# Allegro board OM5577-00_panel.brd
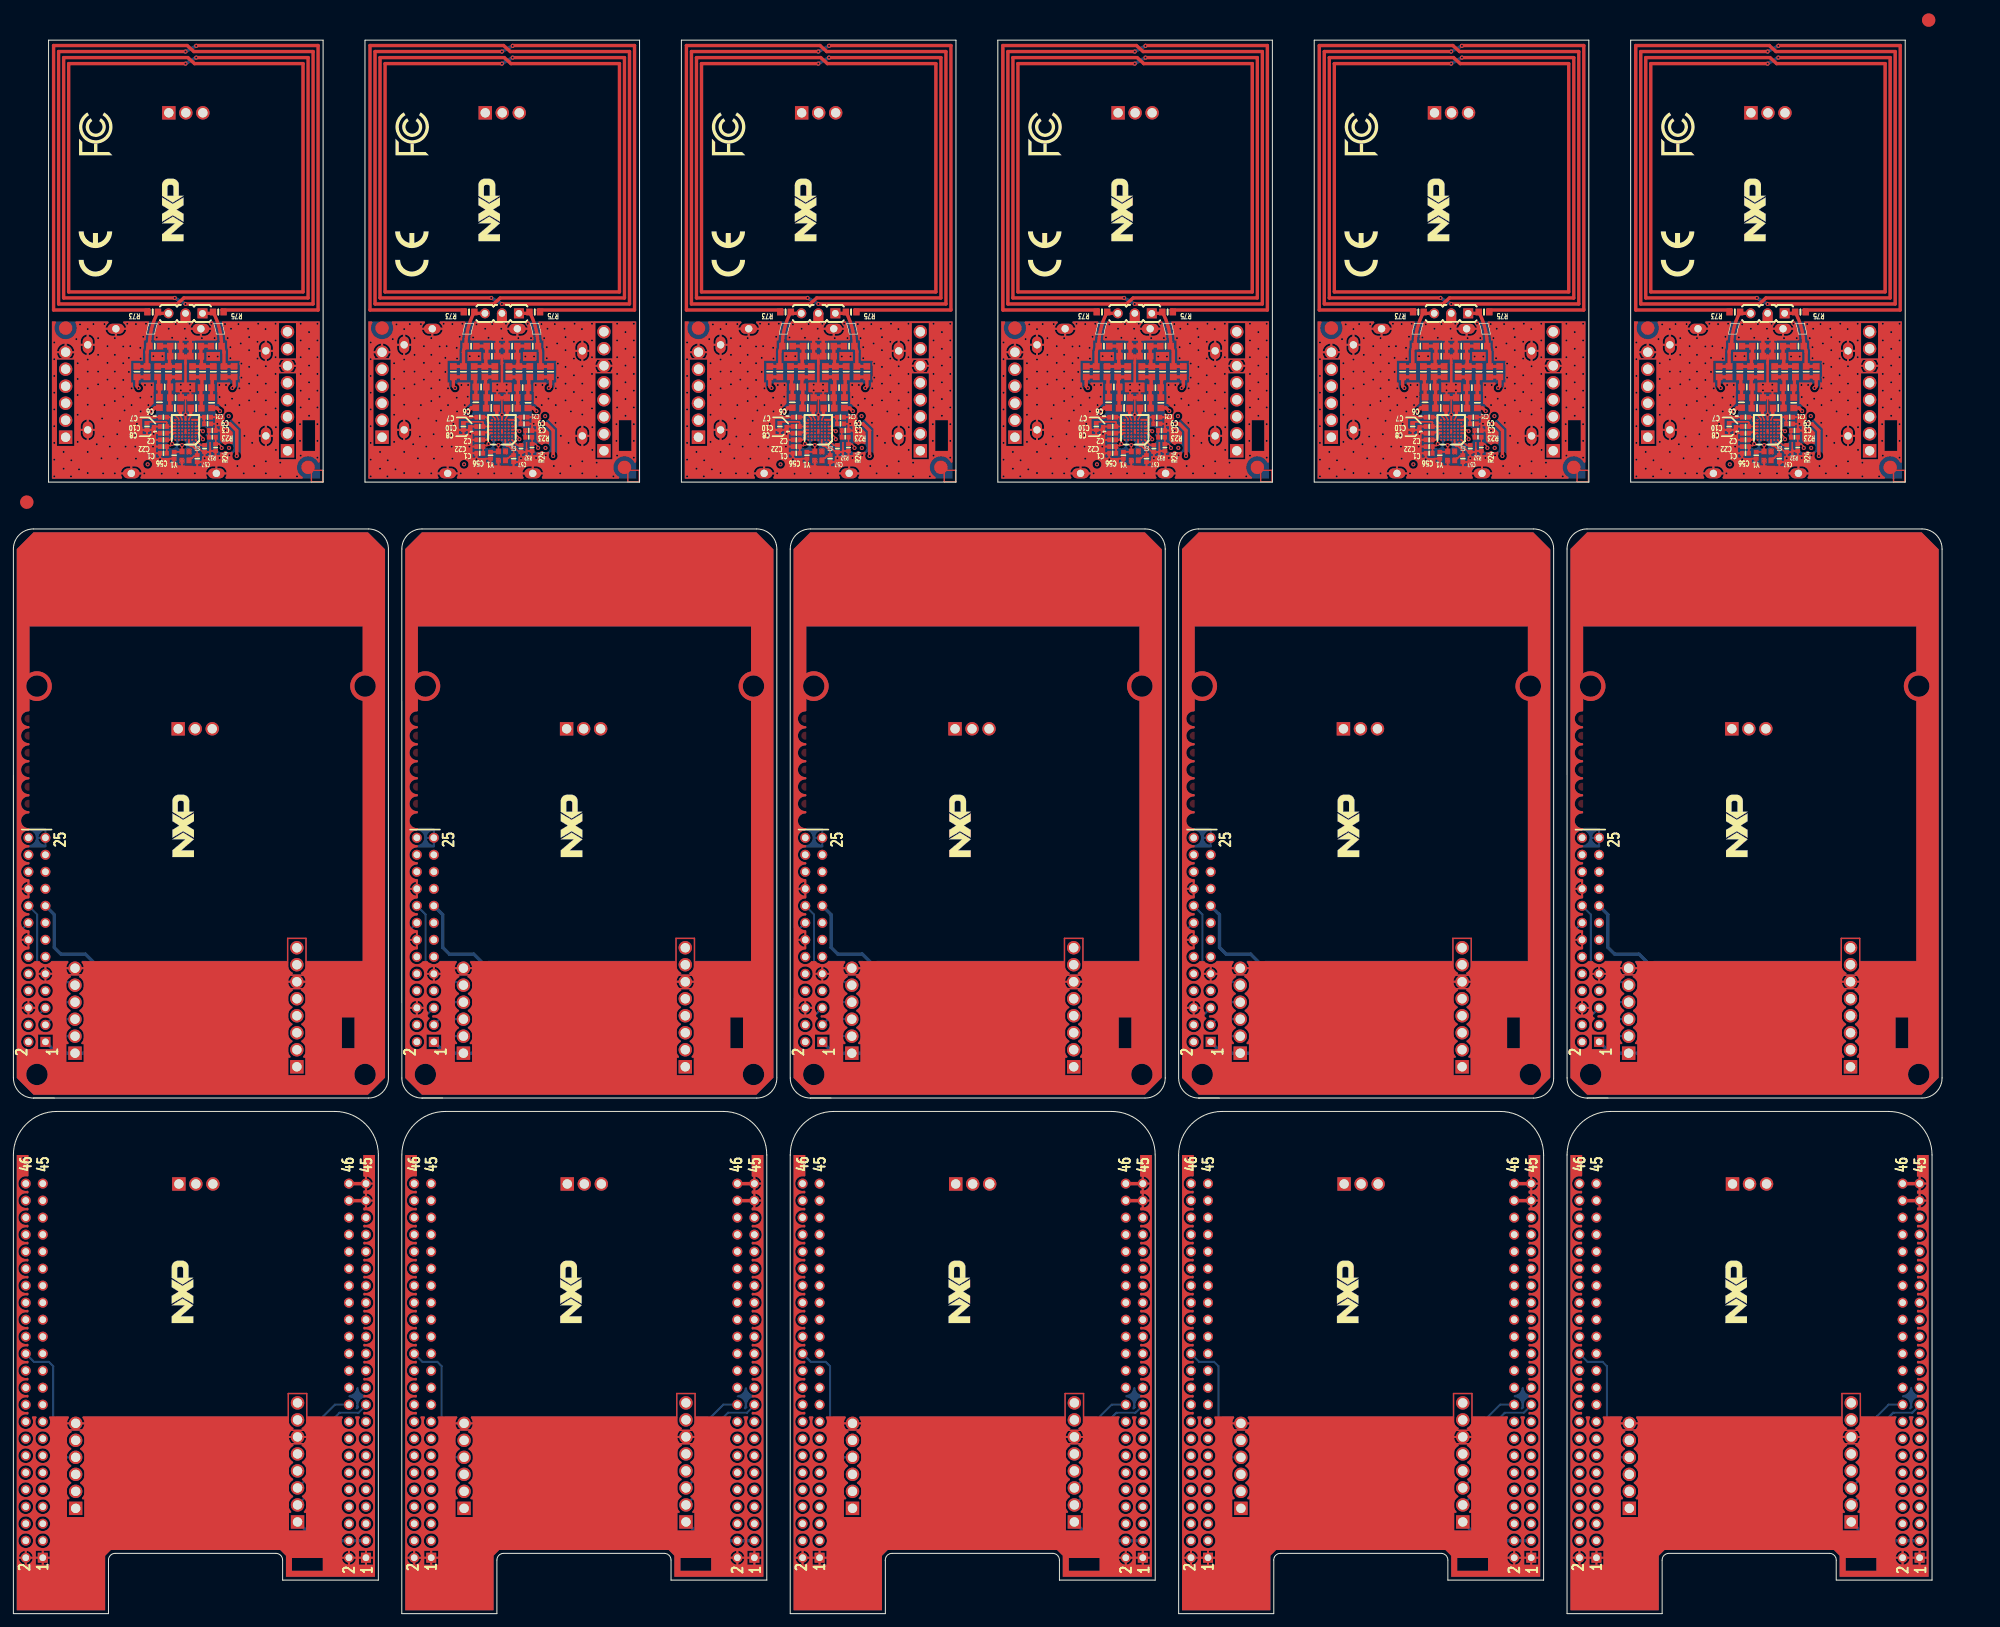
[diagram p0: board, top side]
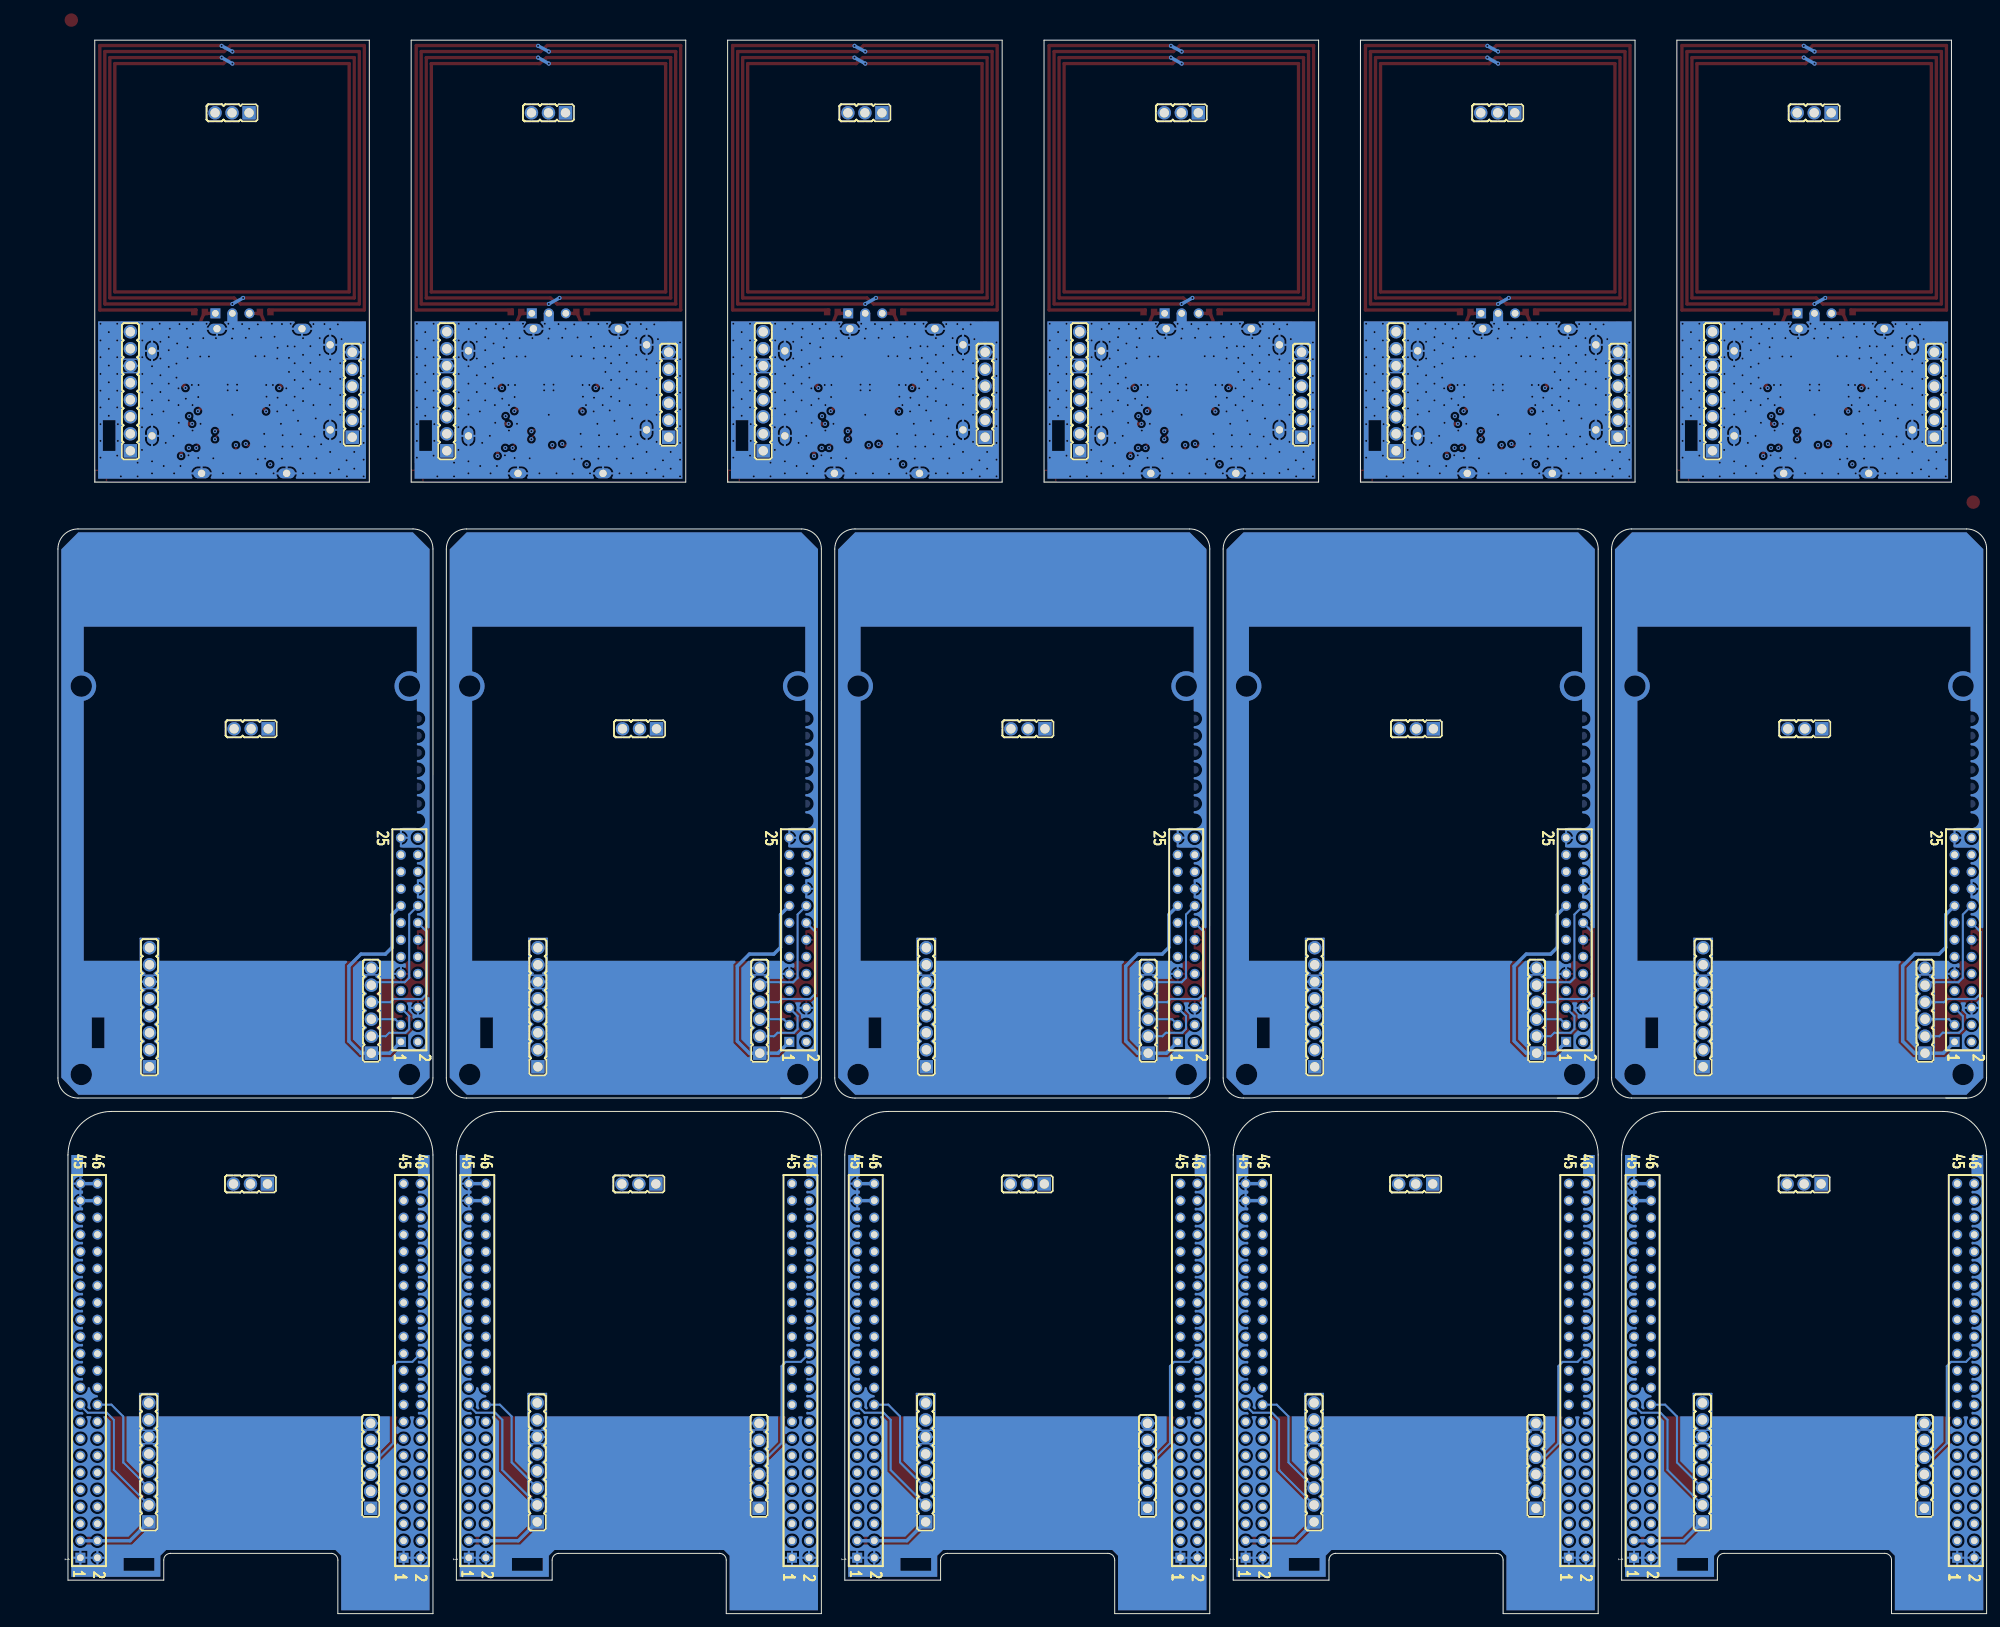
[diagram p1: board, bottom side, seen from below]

Outline 288 x 235 mm; copper layers: TOP, IS1, IS2, BOTTOM. Coordinates in mm from the lower left corner of the outline.
Outline path: 3,77 arc(0.88,77.88) 0,80 0,159 arc(0.88,161.12) 3,162 53,162 arc(55.12,161.12) 56,159 56,80 arc(55.12,77.88) 53,77 3,77 ; 3,77 6.1,77 ; 61,77 arc(58.88,77.88) 58,80 58,159 arc(58.88,161.12) 61,162 111,162 arc(113.12,161.12) 114,159 114,80 arc(113.12,77.88) 111,77 61,77 ; 61,77 64.1,77 ; 119,77 arc(116.88,77.88) 116,80 116,159 arc(116.88,161.12) 119,162 169,162 arc(171.12,161.12) 172,159 172,80 arc(171.12,77.88) 169,77 119,77 ; 119,77 122.1,77 ; 177,77 arc(174.88,77.88) 174,80 174,159 arc(174.88,161.12) 177,162 227,162 arc(229.12,161.12) 230,159 230,80 arc(229.12,77.88) 227,77 177,77 ; 177,77 180.1,77 ; 235,77 arc(232.88,77.88) 232,80 232,159 arc(232.88,161.12) 235,162 285,162 arc(287.12,161.12) 288,159 288,80 arc(287.12,77.88) 285,77 235,77 ; 235,77 238.1,77 ; 0,68.5 0,0 14.2,0 14.2,8 arc(14.49,8.71) 15.2,9 39.2,9 arc(39.91,8.71) 40.2,8 40.2,5 54.5,5 54.5,68.5 arc(52.6,73.1) 48,75 6.5,75 arc(1.9,73.1) 0,68.5 ; 5.25,235 46.25,235 46.25,169 5.25,169 5.25,235 ; 52.5,235 93.5,235 93.5,169 52.5,169 52.5,235 ; 58,68.5 58,0 72.2,0 72.2,8 arc(72.49,8.71) 73.2,9 97.2,9 arc(97.91,8.71) 98.2,8 98.2,5 112.5,5 112.5,68.5 arc(110.6,73.1) 106,75 64.5,75 arc(59.9,73.1) 58,68.5 ; 99.75,235 140.75,235 140.75,169 99.75,169 99.75,235 ; 116,68.5 116,0 130.2,0 130.2,8 arc(130.49,8.71) 131.2,9 155.2,9 arc(155.91,8.71) 156.2,8 156.2,5 170.5,5 170.5,68.5 arc(168.6,73.1) 164,75 122.5,75 arc(117.9,73.1) 116,68.5 ; 147,235 188,235 188,169 147,169 147,235 ; 174,68.5 174,0 188.2,0 188.2,8 arc(188.49,8.71) 189.2,9 213.2,9 arc(213.91,8.71) 214.2,8 214.2,5 228.5,5 228.5,68.5 arc(226.6,73.1) 222,75 180.5,75 arc(175.9,73.1) 174,68.5 ; 194.25,235 235.25,235 235.25,169 194.25,169 194.25,235 ; 232,68.5 232,0 246.2,0 246.2,8 arc(246.49,8.71) 247.2,9 271.2,9 arc(271.91,8.71) 272.2,8 272.2,5 286.5,5 286.5,68.5 arc(284.6,73.1) 280,75 238.5,75 arc(233.9,73.1) 232,68.5 ; 241.5,235 282.5,235 282.5,169 241.5,169 241.5,235

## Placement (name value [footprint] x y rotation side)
A_1_1  BUBBLE1  [BUBBLE_DIAM8]  38.15 162.8 90 top
A_1_C1  1uF  [C0402]  22.4 173.3 180 top
A_1_C2  4.7uF  [C0402]  22.4 175.3 180 top
A_1_C3  1uF  [C0402]  29.7 176.7 0 top
A_1_C6  100nF  [C0402]  22.4 178.7 180 top
A_1_C7  1uF  [C0402]  22.4 177.3 180 top
A_1_C8  470nF  [C0402]  22.4 176.3 180 top
A_1_C9  100nF  [C0402]  29 177.7 0 top
A_1_C10  NC  [C0402]  19.95 177.3 270 top
A_1_C11  39pF/50V  [C0603]  31.45 185.49 90 top
A_1_C12  39pF/50V  [C0603]  19.95 185.49 90 top
A_1_C13  180pF  [C0603]  27.21 181.6 180 top
A_1_C14  180pF  [C0603]  24.21 181.6 180 top
A_1_C15  18pF/50V  [C0603]  28.25 185.49 90 top
A_1_C16  18pF/50V  [C0603]  23.15 185.49 90 top
A_1_C17  10pF/50V  [C0603]  27.21 189.3 180 top
A_1_C18  10pF/50V  [C0603]  24.21 189.3 180 top
A_1_C19  1nF/16V  [C0603]  29.6 180.85 90 top
A_1_C20  1nF/16V  [C0603]  21.8 180.9 90 top
A_1_C21  1uF  [C0402]  29 178.7 0 top
A_1_C22  100nF  [C0402]  22.4 174.3 180 top
A_1_C50  NC  [C0603]  27.21 187.8 180 top
A_1_C51  NC  [C0603]  24.21 187.8 180 top
A_1_C52  NC  [C0603]  18.45 185.49 90 top
A_1_C53  NC  [C0603]  32.95 185.49 90 top
A_1_C54  NC  [C0603]  26.75 185.49 90 top
A_1_C55  NC  [C0603]  24.65 185.49 90 top
A_1_C56  10pF/50V  [C0402]  24 173 270 top
A_1_C57  10pF/50V  [C0402]  27.45 172.5 270 top
A_1_L1  560nH  [SELF_0603]  27.28 180.05 0 top
A_1_L2  560nH  [SELF_0603]  24.12 180.05 180 top
A_1_L104  Antenna  [ANTENNA_4T_40X40]  25.7 192.75 270 top
A_1_R1  2K4  [R0603]  28.79 183.1 0 top
A_1_R2  2K4  [R0603]  22.59 183.2 0 top
A_1_R23  NC  [0402R]  29.7 175.7 180 top
A_1_R24  100K  [0402R]  30.2 174.15 90 top
A_1_R32  100K  [0402R]  28.55 174 90 top
A_1_R53  NC  [R0603]  29.85 185.49 90 top
A_1_R54  NC  [R0603]  21.55 185.49 90 top
A_1_R55  3R3  [R0603]  30.3 189.3 0 top
A_1_R56  3R3  [R0603]  21.1 189.3 180 top
A_1_R73  0R  [R0603]  20.8 194.4 180 top
A_1_R75  0R  [R0603]  30.6 194.4 0 top
A_1_SH1  Shield_27x22mm  [SHIELD_27X22]  11.1 170.3 0 top
A_1_TB1  NC  [BAR_1X3_MD]  28.24 194.2 180 top
A_1_TB2  FORK  [AGPS1-08-BCZ-1MM3]  40.93 173.67 90 bottom
A_1_TB3  FORK  [AGPS1-06-BCZ-1MM3]  7.8 175.7 90 bottom
A_1_TB10  FORK  [AGPS1-03-BCZ-1MM3]  23.21 224.15 0 bottom
A_1_U1  PN7120  [VFBGA49_050_SOT1320-1]  25.7 176.8 270 top
A_1_Y1  NX2016AA_27.12Mhz  [NX2016AA]  25.7 172.9 270 top
A_2_1  BUBBLE1  [BUBBLE_DIAM8]  85.4 162.8 90 top
A_2_C1  1uF  [C0402]  69.65 173.3 180 top
A_2_C2  4.7uF  [C0402]  69.65 175.3 180 top
A_2_C3  1uF  [C0402]  76.95 176.7 0 top
A_2_C6  100nF  [C0402]  69.65 178.7 180 top
A_2_C7  1uF  [C0402]  69.65 177.3 180 top
A_2_C8  470nF  [C0402]  69.65 176.3 180 top
A_2_C9  100nF  [C0402]  76.25 177.7 0 top
A_2_C10  NC  [C0402]  67.2 177.3 270 top
A_2_C11  39pF/50V  [C0603]  78.7 185.49 90 top
A_2_C12  39pF/50V  [C0603]  67.2 185.49 90 top
A_2_C13  180pF  [C0603]  74.46 181.6 180 top
A_2_C14  180pF  [C0603]  71.46 181.6 180 top
A_2_C15  18pF/50V  [C0603]  75.5 185.49 90 top
A_2_C16  18pF/50V  [C0603]  70.4 185.49 90 top
A_2_C17  10pF/50V  [C0603]  74.46 189.3 180 top
A_2_C18  10pF/50V  [C0603]  71.46 189.3 180 top
A_2_C19  1nF/16V  [C0603]  76.85 180.85 90 top
A_2_C20  1nF/16V  [C0603]  69.05 180.9 90 top
A_2_C21  1uF  [C0402]  76.25 178.7 0 top
A_2_C22  100nF  [C0402]  69.65 174.3 180 top
A_2_C50  NC  [C0603]  74.46 187.8 180 top
A_2_C51  NC  [C0603]  71.46 187.8 180 top
A_2_C52  NC  [C0603]  65.7 185.49 90 top
A_2_C53  NC  [C0603]  80.2 185.49 90 top
A_2_C54  NC  [C0603]  74 185.49 90 top
A_2_C55  NC  [C0603]  71.9 185.49 90 top
A_2_C56  10pF/50V  [C0402]  71.25 173 270 top
A_2_C57  10pF/50V  [C0402]  74.7 172.5 270 top
A_2_L1  560nH  [SELF_0603]  74.53 180.05 0 top
A_2_L2  560nH  [SELF_0603]  71.37 180.05 180 top
A_2_L104  Antenna  [ANTENNA_4T_40X40]  72.95 192.75 270 top
A_2_R1  2K4  [R0603]  76.04 183.1 0 top
A_2_R2  2K4  [R0603]  69.84 183.2 0 top
A_2_R23  NC  [0402R]  76.95 175.7 180 top
A_2_R24  100K  [0402R]  77.45 174.15 90 top
A_2_R32  100K  [0402R]  75.8 174 90 top
A_2_R53  NC  [R0603]  77.1 185.49 90 top
A_2_R54  NC  [R0603]  68.8 185.49 90 top
A_2_R55  3R3  [R0603]  77.55 189.3 0 top
A_2_R56  3R3  [R0603]  68.35 189.3 180 top
A_2_R73  0R  [R0603]  68.05 194.4 180 top
A_2_R75  0R  [R0603]  77.85 194.4 0 top
A_2_SH1  Shield_27x22mm  [SHIELD_27X22]  58.35 170.3 0 top
A_2_TB1  NC  [BAR_1X3_MD]  75.49 194.2 180 top
A_2_TB2  FORK  [AGPS1-08-BCZ-1MM3]  88.18 173.67 90 bottom
A_2_TB3  FORK  [AGPS1-06-BCZ-1MM3]  55.05 175.7 90 bottom
A_2_TB10  FORK  [AGPS1-03-BCZ-1MM3]  70.46 224.15 0 bottom
A_2_U1  PN7120  [VFBGA49_050_SOT1320-1]  72.95 176.8 270 top
A_2_Y1  NX2016AA_27.12Mhz  [NX2016AA]  72.95 172.9 270 top
A_3_1  BUBBLE1  [BUBBLE_DIAM8]  132.65 162.8 90 top
A_3_C1  1uF  [C0402]  116.9 173.3 180 top
A_3_C2  4.7uF  [C0402]  116.9 175.3 180 top
A_3_C3  1uF  [C0402]  124.2 176.7 0 top
A_3_C6  100nF  [C0402]  116.9 178.7 180 top
A_3_C7  1uF  [C0402]  116.9 177.3 180 top
A_3_C8  470nF  [C0402]  116.9 176.3 180 top
A_3_C9  100nF  [C0402]  123.5 177.7 0 top
A_3_C10  NC  [C0402]  114.45 177.3 270 top
A_3_C11  39pF/50V  [C0603]  125.95 185.49 90 top
A_3_C12  39pF/50V  [C0603]  114.45 185.49 90 top
A_3_C13  180pF  [C0603]  121.71 181.6 180 top
A_3_C14  180pF  [C0603]  118.71 181.6 180 top
A_3_C15  18pF/50V  [C0603]  122.75 185.49 90 top
A_3_C16  18pF/50V  [C0603]  117.65 185.49 90 top
A_3_C17  10pF/50V  [C0603]  121.71 189.3 180 top
A_3_C18  10pF/50V  [C0603]  118.71 189.3 180 top
A_3_C19  1nF/16V  [C0603]  124.1 180.85 90 top
A_3_C20  1nF/16V  [C0603]  116.3 180.9 90 top
A_3_C21  1uF  [C0402]  123.5 178.7 0 top
A_3_C22  100nF  [C0402]  116.9 174.3 180 top
A_3_C50  NC  [C0603]  121.71 187.8 180 top
A_3_C51  NC  [C0603]  118.71 187.8 180 top
A_3_C52  NC  [C0603]  112.95 185.49 90 top
A_3_C53  NC  [C0603]  127.45 185.49 90 top
A_3_C54  NC  [C0603]  121.25 185.49 90 top
A_3_C55  NC  [C0603]  119.15 185.49 90 top
A_3_C56  10pF/50V  [C0402]  118.5 173 270 top
A_3_C57  10pF/50V  [C0402]  121.95 172.5 270 top
A_3_L1  560nH  [SELF_0603]  121.78 180.05 0 top
A_3_L2  560nH  [SELF_0603]  118.62 180.05 180 top
A_3_L104  Antenna  [ANTENNA_4T_40X40]  120.2 192.75 270 top
A_3_R1  2K4  [R0603]  123.29 183.1 0 top
A_3_R2  2K4  [R0603]  117.09 183.2 0 top
A_3_R23  NC  [0402R]  124.2 175.7 180 top
A_3_R24  100K  [0402R]  124.7 174.15 90 top
A_3_R32  100K  [0402R]  123.05 174 90 top
A_3_R53  NC  [R0603]  124.35 185.49 90 top
A_3_R54  NC  [R0603]  116.05 185.49 90 top
A_3_R55  3R3  [R0603]  124.8 189.3 0 top
A_3_R56  3R3  [R0603]  115.6 189.3 180 top
A_3_R73  0R  [R0603]  115.3 194.4 180 top
A_3_R75  0R  [R0603]  125.1 194.4 0 top
A_3_SH1  Shield_27x22mm  [SHIELD_27X22]  105.6 170.3 0 top
A_3_TB1  NC  [BAR_1X3_MD]  122.74 194.2 180 top
A_3_TB2  FORK  [AGPS1-08-BCZ-1MM3]  135.43 173.67 90 bottom
A_3_TB3  FORK  [AGPS1-06-BCZ-1MM3]  102.3 175.7 90 bottom
A_3_TB10  FORK  [AGPS1-03-BCZ-1MM3]  117.71 224.15 0 bottom
A_3_U1  PN7120  [VFBGA49_050_SOT1320-1]  120.2 176.8 270 top
A_3_Y1  NX2016AA_27.12Mhz  [NX2016AA]  120.2 172.9 270 top
A_4_1  BUBBLE1  [BUBBLE_DIAM8]  179.9 162.8 90 top
A_4_C1  1uF  [C0402]  164.15 173.3 180 top
A_4_C2  4.7uF  [C0402]  164.15 175.3 180 top
A_4_C3  1uF  [C0402]  171.45 176.7 0 top
A_4_C6  100nF  [C0402]  164.15 178.7 180 top
A_4_C7  1uF  [C0402]  164.15 177.3 180 top
A_4_C8  470nF  [C0402]  164.15 176.3 180 top
A_4_C9  100nF  [C0402]  170.75 177.7 0 top
A_4_C10  NC  [C0402]  161.7 177.3 270 top
A_4_C11  39pF/50V  [C0603]  173.2 185.49 90 top
A_4_C12  39pF/50V  [C0603]  161.7 185.49 90 top
A_4_C13  180pF  [C0603]  168.96 181.6 180 top
A_4_C14  180pF  [C0603]  165.96 181.6 180 top
A_4_C15  18pF/50V  [C0603]  170 185.49 90 top
A_4_C16  18pF/50V  [C0603]  164.9 185.49 90 top
A_4_C17  10pF/50V  [C0603]  168.96 189.3 180 top
A_4_C18  10pF/50V  [C0603]  165.96 189.3 180 top
A_4_C19  1nF/16V  [C0603]  171.35 180.85 90 top
A_4_C20  1nF/16V  [C0603]  163.55 180.9 90 top
A_4_C21  1uF  [C0402]  170.75 178.7 0 top
A_4_C22  100nF  [C0402]  164.15 174.3 180 top
A_4_C50  NC  [C0603]  168.96 187.8 180 top
A_4_C51  NC  [C0603]  165.96 187.8 180 top
A_4_C52  NC  [C0603]  160.2 185.49 90 top
A_4_C53  NC  [C0603]  174.7 185.49 90 top
A_4_C54  NC  [C0603]  168.5 185.49 90 top
A_4_C55  NC  [C0603]  166.4 185.49 90 top
A_4_C56  10pF/50V  [C0402]  165.75 173 270 top
A_4_C57  10pF/50V  [C0402]  169.2 172.5 270 top
A_4_L1  560nH  [SELF_0603]  169.03 180.05 0 top
A_4_L2  560nH  [SELF_0603]  165.87 180.05 180 top
A_4_L104  Antenna  [ANTENNA_4T_40X40]  167.45 192.75 270 top
A_4_R1  2K4  [R0603]  170.54 183.1 0 top
A_4_R2  2K4  [R0603]  164.34 183.2 0 top
A_4_R23  NC  [0402R]  171.45 175.7 180 top
A_4_R24  100K  [0402R]  171.95 174.15 90 top
A_4_R32  100K  [0402R]  170.3 174 90 top
A_4_R53  NC  [R0603]  171.6 185.49 90 top
A_4_R54  NC  [R0603]  163.3 185.49 90 top
A_4_R55  3R3  [R0603]  172.05 189.3 0 top
A_4_R56  3R3  [R0603]  162.85 189.3 180 top
A_4_R73  0R  [R0603]  162.55 194.4 180 top
A_4_R75  0R  [R0603]  172.35 194.4 0 top
A_4_SH1  Shield_27x22mm  [SHIELD_27X22]  152.85 170.3 0 top
A_4_TB1  NC  [BAR_1X3_MD]  169.99 194.2 180 top
A_4_TB2  FORK  [AGPS1-08-BCZ-1MM3]  182.68 173.67 90 bottom
A_4_TB3  FORK  [AGPS1-06-BCZ-1MM3]  149.55 175.7 90 bottom
A_4_TB10  FORK  [AGPS1-03-BCZ-1MM3]  164.96 224.15 0 bottom
A_4_U1  PN7120  [VFBGA49_050_SOT1320-1]  167.45 176.8 270 top
A_4_Y1  NX2016AA_27.12Mhz  [NX2016AA]  167.45 172.9 270 top
A_5_1  BUBBLE1  [BUBBLE_DIAM8]  227.15 162.8 90 top
A_5_C1  1uF  [C0402]  211.4 173.3 180 top
A_5_C2  4.7uF  [C0402]  211.4 175.3 180 top
A_5_C3  1uF  [C0402]  218.7 176.7 0 top
A_5_C6  100nF  [C0402]  211.4 178.7 180 top
A_5_C7  1uF  [C0402]  211.4 177.3 180 top
A_5_C8  470nF  [C0402]  211.4 176.3 180 top
A_5_C9  100nF  [C0402]  218 177.7 0 top
A_5_C10  NC  [C0402]  208.95 177.3 270 top
A_5_C11  39pF/50V  [C0603]  220.45 185.49 90 top
A_5_C12  39pF/50V  [C0603]  208.95 185.49 90 top
A_5_C13  180pF  [C0603]  216.21 181.6 180 top
A_5_C14  180pF  [C0603]  213.21 181.6 180 top
A_5_C15  18pF/50V  [C0603]  217.25 185.49 90 top
A_5_C16  18pF/50V  [C0603]  212.15 185.49 90 top
A_5_C17  10pF/50V  [C0603]  216.21 189.3 180 top
A_5_C18  10pF/50V  [C0603]  213.21 189.3 180 top
A_5_C19  1nF/16V  [C0603]  218.6 180.85 90 top
A_5_C20  1nF/16V  [C0603]  210.8 180.9 90 top
A_5_C21  1uF  [C0402]  218 178.7 0 top
A_5_C22  100nF  [C0402]  211.4 174.3 180 top
A_5_C50  NC  [C0603]  216.21 187.8 180 top
A_5_C51  NC  [C0603]  213.21 187.8 180 top
A_5_C52  NC  [C0603]  207.45 185.49 90 top
A_5_C53  NC  [C0603]  221.95 185.49 90 top
A_5_C54  NC  [C0603]  215.75 185.49 90 top
A_5_C55  NC  [C0603]  213.65 185.49 90 top
A_5_C56  10pF/50V  [C0402]  213 173 270 top
A_5_C57  10pF/50V  [C0402]  216.45 172.5 270 top
A_5_L1  560nH  [SELF_0603]  216.28 180.05 0 top
A_5_L2  560nH  [SELF_0603]  213.12 180.05 180 top
A_5_L104  Antenna  [ANTENNA_4T_40X40]  214.7 192.75 270 top
A_5_R1  2K4  [R0603]  217.79 183.1 0 top
A_5_R2  2K4  [R0603]  211.59 183.2 0 top
A_5_R23  NC  [0402R]  218.7 175.7 180 top
A_5_R24  100K  [0402R]  219.2 174.15 90 top
A_5_R32  100K  [0402R]  217.55 174 90 top
A_5_R53  NC  [R0603]  218.85 185.49 90 top
A_5_R54  NC  [R0603]  210.55 185.49 90 top
A_5_R55  3R3  [R0603]  219.3 189.3 0 top
A_5_R56  3R3  [R0603]  210.1 189.3 180 top
A_5_R73  0R  [R0603]  209.8 194.4 180 top
A_5_R75  0R  [R0603]  219.6 194.4 0 top
A_5_SH1  Shield_27x22mm  [SHIELD_27X22]  200.1 170.3 0 top
A_5_TB1  NC  [BAR_1X3_MD]  217.24 194.2 180 top
A_5_TB2  FORK  [AGPS1-08-BCZ-1MM3]  229.93 173.67 90 bottom
A_5_TB3  FORK  [AGPS1-06-BCZ-1MM3]  196.8 175.7 90 bottom
A_5_TB10  FORK  [AGPS1-03-BCZ-1MM3]  212.21 224.15 0 bottom
A_5_U1  PN7120  [VFBGA49_050_SOT1320-1]  214.7 176.8 270 top
A_5_Y1  NX2016AA_27.12Mhz  [NX2016AA]  214.7 172.9 270 top
A_6_1  BUBBLE1  [BUBBLE_DIAM8]  274.4 162.8 90 top
A_6_C1  1uF  [C0402]  258.65 173.3 180 top
A_6_C2  4.7uF  [C0402]  258.65 175.3 180 top
A_6_C3  1uF  [C0402]  265.95 176.7 0 top
A_6_C6  100nF  [C0402]  258.65 178.7 180 top
A_6_C7  1uF  [C0402]  258.65 177.3 180 top
A_6_C8  470nF  [C0402]  258.65 176.3 180 top
A_6_C9  100nF  [C0402]  265.25 177.7 0 top
A_6_C10  NC  [C0402]  256.2 177.3 270 top
A_6_C11  39pF/50V  [C0603]  267.7 185.49 90 top
A_6_C12  39pF/50V  [C0603]  256.2 185.49 90 top
A_6_C13  180pF  [C0603]  263.46 181.6 180 top
A_6_C14  180pF  [C0603]  260.46 181.6 180 top
A_6_C15  18pF/50V  [C0603]  264.5 185.49 90 top
A_6_C16  18pF/50V  [C0603]  259.4 185.49 90 top
A_6_C17  10pF/50V  [C0603]  263.46 189.3 180 top
A_6_C18  10pF/50V  [C0603]  260.46 189.3 180 top
A_6_C19  1nF/16V  [C0603]  265.85 180.85 90 top
A_6_C20  1nF/16V  [C0603]  258.05 180.9 90 top
A_6_C21  1uF  [C0402]  265.25 178.7 0 top
A_6_C22  100nF  [C0402]  258.65 174.3 180 top
A_6_C50  NC  [C0603]  263.46 187.8 180 top
A_6_C51  NC  [C0603]  260.46 187.8 180 top
A_6_C52  NC  [C0603]  254.7 185.49 90 top
A_6_C53  NC  [C0603]  269.2 185.49 90 top
A_6_C54  NC  [C0603]  263 185.49 90 top
A_6_C55  NC  [C0603]  260.9 185.49 90 top
A_6_C56  10pF/50V  [C0402]  260.25 173 270 top
A_6_C57  10pF/50V  [C0402]  263.7 172.5 270 top
A_6_L1  560nH  [SELF_0603]  263.53 180.05 0 top
A_6_L2  560nH  [SELF_0603]  260.37 180.05 180 top
A_6_L104  Antenna  [ANTENNA_4T_40X40]  261.95 192.75 270 top
A_6_R1  2K4  [R0603]  265.04 183.1 0 top
A_6_R2  2K4  [R0603]  258.84 183.2 0 top
A_6_R23  NC  [0402R]  265.95 175.7 180 top
A_6_R24  100K  [0402R]  266.45 174.15 90 top
A_6_R32  100K  [0402R]  264.8 174 90 top
A_6_R53  NC  [R0603]  266.1 185.49 90 top
A_6_R54  NC  [R0603]  257.8 185.49 90 top
A_6_R55  3R3  [R0603]  266.55 189.3 0 top
A_6_R56  3R3  [R0603]  257.35 189.3 180 top
A_6_R73  0R  [R0603]  257.05 194.4 180 top
A_6_R75  0R  [R0603]  266.85 194.4 0 top
A_6_SH1  Shield_27x22mm  [SHIELD_27X22]  247.35 170.3 0 top
A_6_TB1  NC  [BAR_1X3_MD]  264.49 194.2 180 top
A_6_TB2  FORK  [AGPS1-08-BCZ-1MM3]  277.18 173.67 90 bottom
A_6_TB3  FORK  [AGPS1-06-BCZ-1MM3]  244.05 175.7 90 bottom
A_6_TB10  FORK  [AGPS1-03-BCZ-1MM3]  259.46 224.15 0 bottom
A_6_U1  PN7120  [VFBGA49_050_SOT1320-1]  261.95 176.8 270 top
A_6_Y1  NX2016AA_27.12Mhz  [NX2016AA]  261.95 172.9 270 top
B_1_2  BUBBLE2  [BUBBLE_DIAM8]  26.9 2.1 90 top
B_1_J8  bar_2x23_MD_beaglebone_p8  [BAR_2X23_SPE_BEAGLEBONE]  4.39 8.34 90 top
B_1_J9  bar_2x23_MD_beaglebone_p9  [BAR_2X23_SPE_BEAGLEBONE]  52.65 8.34 90 top
B_1_TB8  FORK  [AGPS1-06-BSE]  9.3 15.72 90 bottom
B_1_TB9  FORK  [AGPS1-08-BSE]  42.43 13.69 90 bottom
B_1_TB11  FORK  [AGPS1-03-BSE]  24.71 64.17 0 bottom
B_2_2  BUBBLE2  [BUBBLE_DIAM8]  84.9 2.1 90 top
B_2_J8  bar_2x23_MD_beaglebone_p8  [BAR_2X23_SPE_BEAGLEBONE]  62.39 8.34 90 top
B_2_J9  bar_2x23_MD_beaglebone_p9  [BAR_2X23_SPE_BEAGLEBONE]  110.65 8.34 90 top
B_2_TB8  FORK  [AGPS1-06-BSE]  67.3 15.72 90 bottom
B_2_TB9  FORK  [AGPS1-08-BSE]  100.43 13.69 90 bottom
B_2_TB11  FORK  [AGPS1-03-BSE]  82.71 64.17 0 bottom
B_3_2  BUBBLE2  [BUBBLE_DIAM8]  142.9 2.1 90 top
B_3_J8  bar_2x23_MD_beaglebone_p8  [BAR_2X23_SPE_BEAGLEBONE]  120.39 8.34 90 top
B_3_J9  bar_2x23_MD_beaglebone_p9  [BAR_2X23_SPE_BEAGLEBONE]  168.65 8.34 90 top
B_3_TB8  FORK  [AGPS1-06-BSE]  125.3 15.72 90 bottom
B_3_TB9  FORK  [AGPS1-08-BSE]  158.43 13.69 90 bottom
B_3_TB11  FORK  [AGPS1-03-BSE]  140.71 64.17 0 bottom
B_4_2  BUBBLE2  [BUBBLE_DIAM8]  200.9 2.1 90 top
B_4_J8  bar_2x23_MD_beaglebone_p8  [BAR_2X23_SPE_BEAGLEBONE]  178.39 8.34 90 top
B_4_J9  bar_2x23_MD_beaglebone_p9  [BAR_2X23_SPE_BEAGLEBONE]  226.65 8.34 90 top
B_4_TB8  FORK  [AGPS1-06-BSE]  183.3 15.72 90 bottom
B_4_TB9  FORK  [AGPS1-08-BSE]  216.43 13.69 90 bottom
B_4_TB11  FORK  [AGPS1-03-BSE]  198.71 64.17 0 bottom
B_5_2  BUBBLE2  [BUBBLE_DIAM8]  258.9 2.1 90 top
B_5_J8  bar_2x23_MD_beaglebone_p8  [BAR_2X23_SPE_BEAGLEBONE]  236.39 8.34 90 top
B_5_J9  bar_2x23_MD_beaglebone_p9  [BAR_2X23_SPE_BEAGLEBONE]  284.65 8.34 90 top
B_5_TB8  FORK  [AGPS1-06-BSE]  241.3 15.72 90 bottom
B_5_TB9  FORK  [AGPS1-08-BSE]  274.43 13.69 90 bottom
B_5_TB11  FORK  [AGPS1-03-BSE]  256.71 64.17 0 bottom
C_1_3  BUBBLE3  [BUBBLE_DIAM8]  62.65 115.95 90 top
C_1_4  BUBBLE4(x4)  [BUBBLE_DIAM8]  62.35 81.15 90 top
C_1_5  BUBBLE5(x4)  [BUBBLE_DIAM8]  62.2 89.35 90 top
C_1_6  BUBBLE6(x4)  [BUBBLE_DIAM8]  62.2 97.55 90 top
C_1_J1  bar_2x13_FD_RASPBERRY  [BAR_2X13_FD_SPE_RASPBERRY]  4.79 85.39 90 top
C_1_TB4  FORK  [AGPS1-08-BSE]  42.33 81.67 90 bottom
C_1_TB5  FORK  [AGPS1-06-BSE]  9.2 83.7 90 bottom
C_1_TB12  FORK  [AGPS1-03-BSE]  24.61 132.15 0 bottom
C_2_3  BUBBLE3  [BUBBLE_DIAM8]  120.65 115.95 90 top
C_2_4  BUBBLE4(x4)  [BUBBLE_DIAM8]  120.35 81.15 90 top
C_2_5  BUBBLE5(x4)  [BUBBLE_DIAM8]  120.2 89.35 90 top
C_2_6  BUBBLE6(x4)  [BUBBLE_DIAM8]  120.2 97.55 90 top
C_2_J1  bar_2x13_FD_RASPBERRY  [BAR_2X13_FD_SPE_RASPBERRY]  62.79 85.39 90 top
C_2_TB4  FORK  [AGPS1-08-BSE]  100.33 81.67 90 bottom
C_2_TB5  FORK  [AGPS1-06-BSE]  67.2 83.7 90 bottom
C_2_TB12  FORK  [AGPS1-03-BSE]  82.61 132.15 0 bottom
C_3_3  BUBBLE3  [BUBBLE_DIAM8]  178.65 115.95 90 top
C_3_4  BUBBLE4(x4)  [BUBBLE_DIAM8]  178.35 81.15 90 top
C_3_5  BUBBLE5(x4)  [BUBBLE_DIAM8]  178.2 89.35 90 top
C_3_6  BUBBLE6(x4)  [BUBBLE_DIAM8]  178.2 97.55 90 top
C_3_J1  bar_2x13_FD_RASPBERRY  [BAR_2X13_FD_SPE_RASPBERRY]  120.79 85.39 90 top
C_3_TB4  FORK  [AGPS1-08-BSE]  158.33 81.67 90 bottom
C_3_TB5  FORK  [AGPS1-06-BSE]  125.2 83.7 90 bottom
C_3_TB12  FORK  [AGPS1-03-BSE]  140.61 132.15 0 bottom
C_4_3  BUBBLE3  [BUBBLE_DIAM8]  236.65 115.95 90 top
C_4_4  BUBBLE4(x4)  [BUBBLE_DIAM8]  236.35 81.15 90 top
C_4_5  BUBBLE5(x4)  [BUBBLE_DIAM8]  236.2 89.35 90 top
C_4_6  BUBBLE6(x4)  [BUBBLE_DIAM8]  236.2 97.55 90 top
C_4_J1  bar_2x13_FD_RASPBERRY  [BAR_2X13_FD_SPE_RASPBERRY]  178.79 85.39 90 top
C_4_TB4  FORK  [AGPS1-08-BSE]  216.33 81.67 90 bottom
C_4_TB5  FORK  [AGPS1-06-BSE]  183.2 83.7 90 bottom
C_4_TB12  FORK  [AGPS1-03-BSE]  198.61 132.15 0 bottom
C_5_3  BUBBLE3  [BUBBLE_DIAM8]  294.65 115.95 90 top
C_5_4  BUBBLE4(x4)  [BUBBLE_DIAM8]  294.35 81.15 90 top
C_5_5  BUBBLE5(x4)  [BUBBLE_DIAM8]  294.2 89.35 90 top
C_5_6  BUBBLE6(x4)  [BUBBLE_DIAM8]  294.2 97.55 90 top
C_5_J1  bar_2x13_FD_RASPBERRY  [BAR_2X13_FD_SPE_RASPBERRY]  236.79 85.39 90 top
C_5_TB4  FORK  [AGPS1-08-BSE]  274.33 81.67 90 bottom
C_5_TB5  FORK  [AGPS1-06-BSE]  241.2 83.7 90 bottom
C_5_TB12  FORK  [AGPS1-03-BSE]  256.61 132.15 0 bottom
NOREF  -  []  453.38 148.5 0 top
NOREF#2  -  []  106.8 220.3 90 top
NOREF#3  -  []  59.5 202.2 90 top
NOREF#4  -  [unnamed#2]  7.8 192 90 top
NOREF#5  -  [unnamed#2]  2 166 0 top
NOREF#6  -  []  -0.01 0 90 top
NOREF#7  -  []  0 240 0 top
NOREF#8  -  [unnamed#2]  196.8 192 90 top
NOREF#9  -  [unnamed#2]  185.75 171.2 90 top
NOREF#10  -  []  83.35 117.7 90 top
NOREF#11  -  [unnamed#2]  91.25 171.2 90 top
NOREF#12  -  []  -327 123 0 top
NOREF#13  -  []  326.62 -20.94 0 top
NOREF#14  -  []  248.55 220.3 90 top
NOREF#15  -  [unnamed#2]  244.05 192 90 top
NOREF#16  -  []  118.3 209.7 90 top
NOREF#17  -  []  23.8 209.7 90 top
NOREF#18  -  []  260.05 209.7 90 top
NOREF#19  -  []  154 202.2 90 top
NOREF#20  -  []  165.55 209.7 90 top
NOREF#21  -  []  248.5 202.2 90 top
NOREF#22  -  [unnamed#2]  55.05 192 90 top
NOREF#23  -  []  -39.15 -142.75 0 top
NOREF#24  -  []  199.35 117.7 90 top
NOREF#25  -  [unnamed#2]  44 171.2 90 top
NOREF#26  -  [unnamed#2]  280.25 171.2 90 top
NOREF#27  -  []  141.35 117.7 90 top
NOREF#28  -  []  201.25 202.2 90 top
NOREF#29  -  []  25.35 117.7 90 top
NOREF#30  -  []  12.3 220.3 90 top
NOREF#31  -  []  59.55 220.3 90 top
NOREF#32  -  []  25.25 48.1 90 top
NOREF#33  -  []  83.25 48.1 90 top
NOREF#34  -  [unnamed#2]  149.55 192 90 top
NOREF#35  -  [unnamed#2]  233 171.2 90 top
NOREF#36  -  []  212.8 209.7 90 top
NOREF#37  -  [unnamed#2]  138.5 171.2 90 top
NOREF#38  -  []  141.25 48.1 90 top
NOREF#39  -  []  12.25 202.2 90 top
NOREF#40  -  []  58 -146.25 0 top
NOREF#41  -  []  154.05 220.3 90 top
NOREF#42  -  [unnamed#2]  102.3 192 90 top
NOREF#43  -  []  257.35 117.7 90 top
NOREF#44  -  []  -124.75 -18.25 0 top
NOREF#45  -  []  257.25 48.1 90 top
NOREF#46  -  []  199.25 48.1 90 top
NOREF#47  -  []  201.3 220.3 90 top
NOREF#48  -  []  71.05 209.7 90 top
NOREF#49  -  [unnamed#2]  286 238 0 top
NOREF#50  -  []  106.75 202.2 90 top

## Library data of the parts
A_1_1 A_2_1 A_3_1 A_4_1 A_5_1 A_6_1 B_1_2 B_2_2 B_3_2 B_4_2 B_5_2 C_1_3 C_2_3 C_3_3 C_4_3 C_5_3 = BUBBLE_CI: alternate symbols: (BUBBLE_DIAM4)
A_1_C1-A_1_C3 A_1_C6-A_1_C10 A_1_C21 A_1_C22 A_1_C56 A_1_C57 A_2_C1-A_2_C3 A_2_C6-A_2_C10 A_2_C21 A_2_C22 A_2_C56 A_2_C57 A_3_C1-A_3_C3 A_3_C6-A_3_C10 A_3_C21 A_3_C22 A_3_C56 A_3_C57 A_4_C1-A_4_C3 A_4_C6-A_4_C10 A_4_C21 A_4_C22 A_4_C56 A_4_C57 A_5_C1-A_5_C3 A_5_C6-A_5_C10 A_5_C21 A_5_C22 A_5_C56 A_5_C57 A_6_C1-A_6_C3 A_6_C6-A_6_C10 A_6_C21 A_6_C22 A_6_C56 A_6_C57 = CAP NP: User Part Number: BCNNUMBER; Tolerance: TOLERANCE
A_1_C11-A_1_C20 A_1_C50-A_1_C55 A_2_C11-A_2_C20 A_2_C50-A_2_C55 A_3_C11-A_3_C20 A_3_C50-A_3_C55 A_4_C11-A_4_C20 A_4_C50-A_4_C55 A_5_C11-A_5_C20 A_5_C50-A_5_C55 A_6_C11-A_6_C20 A_6_C50-A_6_C55 = CAP NP: Tolerance: TOLERANCE; User Part Number: PARTNUM
A_1_L1 A_1_L2 A_2_L1 A_2_L2 A_3_L1 A_3_L2 A_4_L1 A_4_L2 A_5_L1 A_5_L2 A_6_L1 A_6_L2 = INDUCTOR: User Part Number: PARTNUM; Tolerance: TOLERANCE
A_1_L104 A_2_L104 A_3_L104 A_4_L104 A_5_L104 A_6_L104 = Antenna
A_1_R1 A_1_R2 A_1_R53-A_1_R56 A_1_R73 A_1_R75 A_2_R1 A_2_R2 A_2_R53-A_2_R56 A_2_R73 A_2_R75 A_3_R1 A_3_R2 A_3_R53-A_3_R56 A_3_R73 A_3_R75 A_4_R1 A_4_R2 A_4_R53-A_4_R56 A_4_R73 A_4_R75 A_5_R1 A_5_R2 A_5_R53-A_5_R56 A_5_R73 A_5_R75 A_6_R1 A_6_R2 A_6_R53-A_6_R56 A_6_R73 A_6_R75 = RESISTOR: User Part Number: PARTNUM; Tolerance: TOLERANCE
A_1_R23 A_1_R24 A_1_R32 A_2_R23 A_2_R24 A_2_R32 A_3_R23 A_3_R24 A_3_R32 A_4_R23 A_4_R24 A_4_R32 A_5_R23 A_5_R24 A_5_R32 A_6_R23 A_6_R24 A_6_R32 = RESISTOR_0: Tolerance: TOLERANCE; User Part Number: BCNNUMBER
A_1_SH1 A_2_SH1 A_3_SH1 A_4_SH1 A_5_SH1 A_6_SH1 = OM5782 Shield_1
A_1_TB1 A_1_TB10 A_2_TB1 A_2_TB10 A_3_TB1 A_3_TB10 A_4_TB1 A_4_TB10 A_5_TB1 A_5_TB10 A_6_TB1 A_6_TB10 B_1_TB11 B_2_TB11 B_3_TB11 B_4_TB11 B_5_TB11 C_1_TB12 C_2_TB12 C_3_TB12 C_4_TB12 C_5_TB12 = bar_1x3_MD: Tolerance: TOLERANCE; User Part Number: PARTNUM
A_1_TB2 A_2_TB2 A_3_TB2 A_4_TB2 A_5_TB2 A_6_TB2 B_1_TB9 B_2_TB9 B_3_TB9 B_4_TB9 B_5_TB9 C_1_TB4 C_2_TB4 C_3_TB4 C_4_TB4 C_5_TB4 = bar_1x8_MD: Tolerance: TOLERANCE; User Part Number: PARTNUM
A_1_TB3 A_2_TB3 A_3_TB3 A_4_TB3 A_5_TB3 A_6_TB3 B_1_TB8 B_2_TB8 B_3_TB8 B_4_TB8 B_5_TB8 C_1_TB5 C_2_TB5 C_3_TB5 C_4_TB5 C_5_TB5 = bar_1x6_MD: Tolerance: TOLERANCE; User Part Number: PARTNUM
A_1_U1 A_2_U1 A_3_U1 A_4_U1 A_5_U1 A_6_U1 = PN7120_VFBGA49
A_1_Y1 A_2_Y1 A_3_Y1 A_4_Y1 A_5_Y1 A_6_Y1 = NX2016AA_xMhz
B_1_J8 B_2_J8 B_3_J8 B_4_J8 B_5_J8 = bar_2x23_MD_beaglebone_p8: Tolerance: TOLERANCE; User Part Number: PARTNUM
B_1_J9 B_2_J9 B_3_J9 B_4_J9 B_5_J9 = bar_2x23_MD_beaglebone_p9_1: Tolerance: TOLERANCE; User Part Number: PARTNUM
C_1_4 C_2_4 C_3_4 C_4_4 C_5_4 = BUBBLE_entretoise_nylon_M3x20: alternate symbols: (BUBBLE_DIAM4)
C_1_5 C_2_5 C_3_5 C_4_5 C_5_5 = BUBBLE_RONDELLE_M3_PLATE: alternate symbols: (BUBBLE_DIAM4)
C_1_6 C_2_6 C_3_6 C_4_6 C_5_6 = BUBBLE_VIS_M3X6: alternate symbols: (BUBBLE_DIAM4)
C_1_J1 C_2_J1 C_3_J1 C_4_J1 C_5_J1 = bar_2x13_FD_RASPBERRY_0: Tolerance: TOLERANCE; User Part Number: PARTNUM

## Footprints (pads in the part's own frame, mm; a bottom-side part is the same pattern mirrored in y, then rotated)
0402R
  rect 0.61x0.711 smd: 1(-0.508,0) 2(0.508,0)
AGPS1-03-BCZ-1MM3
  rect 2x2 hole 1.4: 1(0,0)
  round 2 hole 1.4: 2(2.54,0) 3(5.08,0)
AGPS1-03-BSE
  rect 2x2 hole 1.4: 1(0,0)
  round 2 hole 1.4: 2(2.54,0) 3(5.08,0)
AGPS1-06-BCZ-1MM3
  rect 2x2 hole 1.4: 1(0,0)
  round 2 hole 1.4: 2(2.54,0) 3(5.08,0) 4(7.62,0) 5(10.16,0) 6(12.7,0)
AGPS1-06-BSE
  rect 2x2 hole 1.4: 1(0,0)
  round 2 hole 1.4: 2(2.54,0) 3(5.08,0) 4(7.62,0) 5(10.16,0) 6(12.7,0)
AGPS1-08-BCZ-1MM3
  rect 2x2 hole 1.4: 1(0,0)
  round 2 hole 1.4: 2(2.54,0) 3(5.08,0) 4(7.62,0) 5(10.16,0) 6(12.7,0) 7(15.24,0) 8(17.78,0)
AGPS1-08-BSE
  rect 2x2 hole 1.4: 1(0,0)
  round 2 hole 1.4: 2(2.54,0) 3(5.08,0) 4(7.62,0) 5(10.16,0) 6(12.7,0) 7(15.24,0) 8(17.78,0)
ANTENNA_4T_40X40
  round 0.5 smd: 1(-1.95,5.45) 2(-1.95,-5.45)
BAR_1X3_MD
  rect 1.49x1.49 hole 1: 1(0,0)
  round 1.49 hole 1: 2(2.54,0) 3(5.08,0)
BAR_2X13_FD_SPE_RASPBERRY
  rect 1.49x1.49 hole 1: 1(0,0)
  round 1.49 hole 1: 2(0,2.54) 3(2.54,0) 4(2.54,2.54) 5(5.08,0) 6(5.08,2.54) 7(7.62,0) 8(7.62,2.54) 9(10.16,0) 10(10.16,2.54) 11(12.7,0) 12(12.7,2.54) 13(15.24,0) 14(15.24,2.54) 15(17.78,0) 16(17.78,2.54) 17(20.32,0) 18(20.32,2.54) 19(22.86,0) 20(22.86,2.54) 21(25.4,0) 22(25.4,2.54) 23(27.94,0) 24(27.94,2.54) 25(30.48,0) 26(30.48,2.54)
BAR_2X23_SPE_BEAGLEBONE
  rect 1.49x1.49 hole 1: C1(0,0)
  round 1.49 hole 1: C2(0,2.54) C3(2.54,0) C4(2.54,2.54) C5(5.08,0) C6(5.08,2.54) C7(7.62,0) C8(7.62,2.54) C9(10.16,0) C10(10.16,2.54) C11(12.7,0) C12(12.7,2.54) C13(15.24,0) C14(15.24,2.54) C15(17.78,0) C16(17.78,2.54) C17(20.32,0) C18(20.32,2.54) C19(22.86,0) C20(22.86,2.54) C21(25.4,0) C22(25.4,2.54) C23(27.94,0) C24(27.94,2.54) C25(30.48,0) C26(30.48,2.54) C27(33.02,0) C28(33.02,2.54) C29(35.56,0) C30(35.56,2.54) C31(38.1,0) C32(38.1,2.54) C33(40.64,0) C34(40.64,2.54) C35(43.18,0) C36(43.18,2.54) C37(45.72,0) C38(45.72,2.54) C39(48.26,0) C40(48.26,2.54) C41(50.8,0) C42(50.8,2.54) C43(53.34,0) C44(53.34,2.54) C45(55.88,0) C46(55.88,2.54)
BUBBLE_DIAM8
  round 0 smd: 1(0,0)
C0402
  rect 0.61x0.711 smd: 1(-0.508,0) 2(0.508,0)
C0603
  rect 0.965x1.016 smd: 1(-0.787,0) 2(0.787,0)
NX2016AA
  rect 0.85x0.75 smd: 1(-0.675,-0.525) 3(0.675,0.525) 4(-0.675,0.525)
  custom 0.188x0.188 smd: 2(0.675,-0.525)
R0603
  rect 0.965x1.016 smd: 1(-0.787,0) 2(0.787,0)
SELF_0603
  rect 0.965x1.016 smd: 1(-0.787,0) 2(0.787,0)
SHIELD_27X22
  oval 1.5x2.5 hole 1.1: 1(0,6.5) 4(26.6,5.6) 5(26.6,18.3) 8(0,19.2)
  oval 2.5x1.5 hole 1.1: 2(6.5,0) 3(19.2,0) 6(16.9,21.6) 7(4.2,21.6)
unnamed#2
  round 2 smd: (0,0)
VFBGA49_050_SOT1320-1
  round 0.3 smd: A1(1.5,1.5) A2(1.5,1) A3(1.5,0.5) A4(1.5,0) A5(1.5,-0.5) A6(1.5,-1) A7(1.5,-1.5) B1(1,1.5) B2(1,1) B3(1,0.5) B4(1,0) B5(1,-0.5) B6(1,-1) B7(1,-1.5) C1(0.5,1.5) C2(0.5,1) C3(0.5,0.5) C4(0.5,0) C5(0.5,-0.5) C6(0.5,-1) C7(0.5,-1.5) D1(0,1.5) D2(0,1) D3(0,0.5) D4(0,0) D5(0,-0.5) D6(0,-1) D7(0,-1.5) E1(-0.5,1.5) E2(-0.5,1) E3(-0.5,0.5) E4(-0.5,0) E5(-0.5,-0.5) E6(-0.5,-1) E7(-0.5,-1.5) F1(-1,1.5) F2(-1,1) F3(-1,0.5) F4(-1,0) F5(-1,-0.5) F6(-1,-1) F7(-1,-1.5) G1(-1.5,1.5) G2(-1.5,1) G3(-1.5,0.5) G4(-1.5,0) G5(-1.5,-0.5) G6(-1.5,-1) G7(-1.5,-1.5)

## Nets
A_1_ANT1: A_1_C11.1 A_1_C53.1 A_1_U1.G7(ANT1)
A_1_ANT2: A_1_C12.1 A_1_C52.1 A_1_U1.G6(ANT2)
A_1_GND: A_1_C1.2 A_1_C2.2 A_1_C3.2 A_1_C6.2 A_1_C7.2 A_1_C8.2 A_1_C9.2 A_1_C10.2 A_1_C13.2 A_1_C14.1 A_1_C17.2 A_1_C18.1 A_1_C21.2 A_1_C22.2 A_1_C50.2 A_1_C51.1 A_1_C56.2 A_1_C57.2 A_1_R24.1 A_1_R32.1 A_1_SH1.1 A_1_SH1.2 A_1_SH1.3 A_1_SH1.4 A_1_SH1.5 A_1_SH1.6 A_1_SH1.7 A_1_SH1.8 A_1_TB1.2 A_1_TB2.6 A_1_TB3.6 A_1_U1.B5(TST2) A_1_U1.B6(VSS1) A_1_U1.C2(PVSS) A_1_U1.C4(VSS) A_1_U1.D4(VSS2) A_1_U1.D6(VSS3) A_1_U1.E2(DCDC_VSS) A_1_U1.F3(VSS4) A_1_U1.G4(TVSS) A_1_Y1.2(#2) A_1_Y1.4(#4)
A_1_I2C_SCL: A_1_TB2.2 A_1_TB3.2 A_1_U1.B1(I2CSCL)
A_1_I2C_SDA: A_1_TB2.3 A_1_TB3.3 A_1_U1.C1(I2CSDA)
A_1_IRQ: A_1_TB2.4 A_1_TB3.4 A_1_U1.D1(IRQ)
A_1_N2189999: A_1_C15.2 A_1_C17.1 A_1_C50.1 A_1_C54.2 A_1_R53.2 A_1_R55.1
A_1_N2190055: A_1_C16.2 A_1_C18.2 A_1_C51.2 A_1_C55.2 A_1_R54.2 A_1_R56.1
A_1_N2190079: A_1_C13.1 A_1_C15.1 A_1_C54.1 A_1_L1.2 A_1_R1.1
A_1_N2190159: A_1_C12.2 A_1_C52.2 A_1_R56.2 A_1_R73.1 A_1_TB1.3
A_1_N2190199: A_1_C11.2 A_1_C53.2 A_1_R55.2 A_1_R75.1 A_1_TB1.1
A_1_N2190513: A_1_C14.2 A_1_C16.1 A_1_C55.1 A_1_L2.2 A_1_R2.2
A_1_N2190991: A_1_L104.1 A_1_L104.2 A_1_R73.2 A_1_R75.2
A_1_N2198580: A_1_R23.1 A_1_R24.2 A_1_U1.B2(I2CADR0)
A_1_N2222470: A_1_C20.2 A_1_R2.1 A_1_R54.1
A_1_N2227379: A_1_C19.2 A_1_R1.2 A_1_R53.1
A_1_N2256986: A_1_C57.1 A_1_U1.A3(XTAL1) A_1_Y1.3(#3)
A_1_N2256988: A_1_C56.1 A_1_U1.C3(XTAL2) A_1_Y1.1(#1)
A_1_N2257197: A_1_R32.2 A_1_U1.A1(TST1)
A_1_N2257995: A_1_C1.1 A_1_C22.1 A_1_U1.C6(VDD)
A_1_N2259746: A_1_C7.1 A_1_C10.1 A_1_U1.E7(TVDD)
A_1_N2259753: A_1_C8.1 A_1_U1.D7(VDHF)
A_1_N2259760: A_1_C6.1 A_1_U1.F7(VMID)
A_1_PVDD: A_1_C2.1 A_1_C3.1 A_1_C9.1 A_1_C21.1 A_1_R23.2 A_1_TB2.1 A_1_TB3.1 A_1_U1.C7(VBAT) A_1_U1.D3(PVDD) A_1_U1.G1(VBAT2) A_1_U1.G2(VUP)
A_1_RXN: A_1_C20.1 A_1_U1.F5(RXN)
A_1_RXP: A_1_C19.1 A_1_U1.F6(RXP)
A_1_TX1: A_1_L1.1 A_1_U1.G3(TX1)
A_1_TX2: A_1_L2.1 A_1_U1.G5(TX2)
A_1_VEN: A_1_TB2.5 A_1_TB3.5 A_1_U1.E1(VEN)
A_2_ANT1: A_2_C11.1 A_2_C53.1 A_2_U1.G7(ANT1)
A_2_ANT2: A_2_C12.1 A_2_C52.1 A_2_U1.G6(ANT2)
A_2_GND: A_2_C1.2 A_2_C2.2 A_2_C3.2 A_2_C6.2 A_2_C7.2 A_2_C8.2 A_2_C9.2 A_2_C10.2 A_2_C13.2 A_2_C14.1 A_2_C17.2 A_2_C18.1 A_2_C21.2 A_2_C22.2 A_2_C50.2 A_2_C51.1 A_2_C56.2 A_2_C57.2 A_2_R24.1 A_2_R32.1 A_2_SH1.1 A_2_SH1.2 A_2_SH1.3 A_2_SH1.4 A_2_SH1.5 A_2_SH1.6 A_2_SH1.7 A_2_SH1.8 A_2_TB1.2 A_2_TB2.6 A_2_TB3.6 A_2_U1.B5(TST2) A_2_U1.B6(VSS1) A_2_U1.C2(PVSS) A_2_U1.C4(VSS) A_2_U1.D4(VSS2) A_2_U1.D6(VSS3) A_2_U1.E2(DCDC_VSS) A_2_U1.F3(VSS4) A_2_U1.G4(TVSS) A_2_Y1.2(#2) A_2_Y1.4(#4)
A_2_I2C_SCL: A_2_TB2.2 A_2_TB3.2 A_2_U1.B1(I2CSCL)
A_2_I2C_SDA: A_2_TB2.3 A_2_TB3.3 A_2_U1.C1(I2CSDA)
A_2_IRQ: A_2_TB2.4 A_2_TB3.4 A_2_U1.D1(IRQ)
A_2_N2189999: A_2_C15.2 A_2_C17.1 A_2_C50.1 A_2_C54.2 A_2_R53.2 A_2_R55.1
A_2_N2190055: A_2_C16.2 A_2_C18.2 A_2_C51.2 A_2_C55.2 A_2_R54.2 A_2_R56.1
A_2_N2190079: A_2_C13.1 A_2_C15.1 A_2_C54.1 A_2_L1.2 A_2_R1.1
A_2_N2190159: A_2_C12.2 A_2_C52.2 A_2_R56.2 A_2_R73.1 A_2_TB1.3
A_2_N2190199: A_2_C11.2 A_2_C53.2 A_2_R55.2 A_2_R75.1 A_2_TB1.1
A_2_N2190513: A_2_C14.2 A_2_C16.1 A_2_C55.1 A_2_L2.2 A_2_R2.2
A_2_N2190991: A_2_L104.1 A_2_L104.2 A_2_R73.2 A_2_R75.2
A_2_N2198580: A_2_R23.1 A_2_R24.2 A_2_U1.B2(I2CADR0)
A_2_N2222470: A_2_C20.2 A_2_R2.1 A_2_R54.1
A_2_N2227379: A_2_C19.2 A_2_R1.2 A_2_R53.1
A_2_N2256986: A_2_C57.1 A_2_U1.A3(XTAL1) A_2_Y1.3(#3)
A_2_N2256988: A_2_C56.1 A_2_U1.C3(XTAL2) A_2_Y1.1(#1)
A_2_N2257197: A_2_R32.2 A_2_U1.A1(TST1)
A_2_N2257995: A_2_C1.1 A_2_C22.1 A_2_U1.C6(VDD)
A_2_N2259746: A_2_C7.1 A_2_C10.1 A_2_U1.E7(TVDD)
A_2_N2259753: A_2_C8.1 A_2_U1.D7(VDHF)
A_2_N2259760: A_2_C6.1 A_2_U1.F7(VMID)
A_2_PVDD: A_2_C2.1 A_2_C3.1 A_2_C9.1 A_2_C21.1 A_2_R23.2 A_2_TB2.1 A_2_TB3.1 A_2_U1.C7(VBAT) A_2_U1.D3(PVDD) A_2_U1.G1(VBAT2) A_2_U1.G2(VUP)
A_2_RXN: A_2_C20.1 A_2_U1.F5(RXN)
A_2_RXP: A_2_C19.1 A_2_U1.F6(RXP)
A_2_TX1: A_2_L1.1 A_2_U1.G3(TX1)
A_2_TX2: A_2_L2.1 A_2_U1.G5(TX2)
A_2_VEN: A_2_TB2.5 A_2_TB3.5 A_2_U1.E1(VEN)
A_3_ANT1: A_3_C11.1 A_3_C53.1 A_3_U1.G7(ANT1)
A_3_ANT2: A_3_C12.1 A_3_C52.1 A_3_U1.G6(ANT2)
A_3_GND: A_3_C1.2 A_3_C2.2 A_3_C3.2 A_3_C6.2 A_3_C7.2 A_3_C8.2 A_3_C9.2 A_3_C10.2 A_3_C13.2 A_3_C14.1 A_3_C17.2 A_3_C18.1 A_3_C21.2 A_3_C22.2 A_3_C50.2 A_3_C51.1 A_3_C56.2 A_3_C57.2 A_3_R24.1 A_3_R32.1 A_3_SH1.1 A_3_SH1.2 A_3_SH1.3 A_3_SH1.4 A_3_SH1.5 A_3_SH1.6 A_3_SH1.7 A_3_SH1.8 A_3_TB1.2 A_3_TB2.6 A_3_TB3.6 A_3_U1.B5(TST2) A_3_U1.B6(VSS1) A_3_U1.C2(PVSS) A_3_U1.C4(VSS) A_3_U1.D4(VSS2) A_3_U1.D6(VSS3) A_3_U1.E2(DCDC_VSS) A_3_U1.F3(VSS4) A_3_U1.G4(TVSS) A_3_Y1.2(#2) A_3_Y1.4(#4)
A_3_I2C_SCL: A_3_TB2.2 A_3_TB3.2 A_3_U1.B1(I2CSCL)
A_3_I2C_SDA: A_3_TB2.3 A_3_TB3.3 A_3_U1.C1(I2CSDA)
A_3_IRQ: A_3_TB2.4 A_3_TB3.4 A_3_U1.D1(IRQ)
A_3_N2189999: A_3_C15.2 A_3_C17.1 A_3_C50.1 A_3_C54.2 A_3_R53.2 A_3_R55.1
A_3_N2190055: A_3_C16.2 A_3_C18.2 A_3_C51.2 A_3_C55.2 A_3_R54.2 A_3_R56.1
A_3_N2190079: A_3_C13.1 A_3_C15.1 A_3_C54.1 A_3_L1.2 A_3_R1.1
A_3_N2190159: A_3_C12.2 A_3_C52.2 A_3_R56.2 A_3_R73.1 A_3_TB1.3
A_3_N2190199: A_3_C11.2 A_3_C53.2 A_3_R55.2 A_3_R75.1 A_3_TB1.1
A_3_N2190513: A_3_C14.2 A_3_C16.1 A_3_C55.1 A_3_L2.2 A_3_R2.2
A_3_N2190991: A_3_L104.1 A_3_L104.2 A_3_R73.2 A_3_R75.2
A_3_N2198580: A_3_R23.1 A_3_R24.2 A_3_U1.B2(I2CADR0)
A_3_N2222470: A_3_C20.2 A_3_R2.1 A_3_R54.1
A_3_N2227379: A_3_C19.2 A_3_R1.2 A_3_R53.1
A_3_N2256986: A_3_C57.1 A_3_U1.A3(XTAL1) A_3_Y1.3(#3)
A_3_N2256988: A_3_C56.1 A_3_U1.C3(XTAL2) A_3_Y1.1(#1)
A_3_N2257197: A_3_R32.2 A_3_U1.A1(TST1)
A_3_N2257995: A_3_C1.1 A_3_C22.1 A_3_U1.C6(VDD)
A_3_N2259746: A_3_C7.1 A_3_C10.1 A_3_U1.E7(TVDD)
A_3_N2259753: A_3_C8.1 A_3_U1.D7(VDHF)
A_3_N2259760: A_3_C6.1 A_3_U1.F7(VMID)
A_3_PVDD: A_3_C2.1 A_3_C3.1 A_3_C9.1 A_3_C21.1 A_3_R23.2 A_3_TB2.1 A_3_TB3.1 A_3_U1.C7(VBAT) A_3_U1.D3(PVDD) A_3_U1.G1(VBAT2) A_3_U1.G2(VUP)
A_3_RXN: A_3_C20.1 A_3_U1.F5(RXN)
A_3_RXP: A_3_C19.1 A_3_U1.F6(RXP)
A_3_TX1: A_3_L1.1 A_3_U1.G3(TX1)
A_3_TX2: A_3_L2.1 A_3_U1.G5(TX2)
A_3_VEN: A_3_TB2.5 A_3_TB3.5 A_3_U1.E1(VEN)
A_4_ANT1: A_4_C11.1 A_4_C53.1 A_4_U1.G7(ANT1)
A_4_ANT2: A_4_C12.1 A_4_C52.1 A_4_U1.G6(ANT2)
A_4_GND: A_4_C1.2 A_4_C2.2 A_4_C3.2 A_4_C6.2 A_4_C7.2 A_4_C8.2 A_4_C9.2 A_4_C10.2 A_4_C13.2 A_4_C14.1 A_4_C17.2 A_4_C18.1 A_4_C21.2 A_4_C22.2 A_4_C50.2 A_4_C51.1 A_4_C56.2 A_4_C57.2 A_4_R24.1 A_4_R32.1 A_4_SH1.1 A_4_SH1.2 A_4_SH1.3 A_4_SH1.4 A_4_SH1.5 A_4_SH1.6 A_4_SH1.7 A_4_SH1.8 A_4_TB1.2 A_4_TB2.6 A_4_TB3.6 A_4_U1.B5(TST2) A_4_U1.B6(VSS1) A_4_U1.C2(PVSS) A_4_U1.C4(VSS) A_4_U1.D4(VSS2) A_4_U1.D6(VSS3) A_4_U1.E2(DCDC_VSS) A_4_U1.F3(VSS4) A_4_U1.G4(TVSS) A_4_Y1.2(#2) A_4_Y1.4(#4)
A_4_I2C_SCL: A_4_TB2.2 A_4_TB3.2 A_4_U1.B1(I2CSCL)
A_4_I2C_SDA: A_4_TB2.3 A_4_TB3.3 A_4_U1.C1(I2CSDA)
A_4_IRQ: A_4_TB2.4 A_4_TB3.4 A_4_U1.D1(IRQ)
A_4_N2189999: A_4_C15.2 A_4_C17.1 A_4_C50.1 A_4_C54.2 A_4_R53.2 A_4_R55.1
A_4_N2190055: A_4_C16.2 A_4_C18.2 A_4_C51.2 A_4_C55.2 A_4_R54.2 A_4_R56.1
A_4_N2190079: A_4_C13.1 A_4_C15.1 A_4_C54.1 A_4_L1.2 A_4_R1.1
A_4_N2190159: A_4_C12.2 A_4_C52.2 A_4_R56.2 A_4_R73.1 A_4_TB1.3
A_4_N2190199: A_4_C11.2 A_4_C53.2 A_4_R55.2 A_4_R75.1 A_4_TB1.1
A_4_N2190513: A_4_C14.2 A_4_C16.1 A_4_C55.1 A_4_L2.2 A_4_R2.2
A_4_N2190991: A_4_L104.1 A_4_L104.2 A_4_R73.2 A_4_R75.2
A_4_N2198580: A_4_R23.1 A_4_R24.2 A_4_U1.B2(I2CADR0)
A_4_N2222470: A_4_C20.2 A_4_R2.1 A_4_R54.1
A_4_N2227379: A_4_C19.2 A_4_R1.2 A_4_R53.1
A_4_N2256986: A_4_C57.1 A_4_U1.A3(XTAL1) A_4_Y1.3(#3)
A_4_N2256988: A_4_C56.1 A_4_U1.C3(XTAL2) A_4_Y1.1(#1)
A_4_N2257197: A_4_R32.2 A_4_U1.A1(TST1)
A_4_N2257995: A_4_C1.1 A_4_C22.1 A_4_U1.C6(VDD)
A_4_N2259746: A_4_C7.1 A_4_C10.1 A_4_U1.E7(TVDD)
A_4_N2259753: A_4_C8.1 A_4_U1.D7(VDHF)
A_4_N2259760: A_4_C6.1 A_4_U1.F7(VMID)
A_4_PVDD: A_4_C2.1 A_4_C3.1 A_4_C9.1 A_4_C21.1 A_4_R23.2 A_4_TB2.1 A_4_TB3.1 A_4_U1.C7(VBAT) A_4_U1.D3(PVDD) A_4_U1.G1(VBAT2) A_4_U1.G2(VUP)
A_4_RXN: A_4_C20.1 A_4_U1.F5(RXN)
A_4_RXP: A_4_C19.1 A_4_U1.F6(RXP)
A_4_TX1: A_4_L1.1 A_4_U1.G3(TX1)
A_4_TX2: A_4_L2.1 A_4_U1.G5(TX2)
A_4_VEN: A_4_TB2.5 A_4_TB3.5 A_4_U1.E1(VEN)
A_5_ANT1: A_5_C11.1 A_5_C53.1 A_5_U1.G7(ANT1)
A_5_ANT2: A_5_C12.1 A_5_C52.1 A_5_U1.G6(ANT2)
A_5_GND: A_5_C1.2 A_5_C2.2 A_5_C3.2 A_5_C6.2 A_5_C7.2 A_5_C8.2 A_5_C9.2 A_5_C10.2 A_5_C13.2 A_5_C14.1 A_5_C17.2 A_5_C18.1 A_5_C21.2 A_5_C22.2 A_5_C50.2 A_5_C51.1 A_5_C56.2 A_5_C57.2 A_5_R24.1 A_5_R32.1 A_5_SH1.1 A_5_SH1.2 A_5_SH1.3 A_5_SH1.4 A_5_SH1.5 A_5_SH1.6 A_5_SH1.7 A_5_SH1.8 A_5_TB1.2 A_5_TB2.6 A_5_TB3.6 A_5_U1.B5(TST2) A_5_U1.B6(VSS1) A_5_U1.C2(PVSS) A_5_U1.C4(VSS) A_5_U1.D4(VSS2) A_5_U1.D6(VSS3) A_5_U1.E2(DCDC_VSS) A_5_U1.F3(VSS4) A_5_U1.G4(TVSS) A_5_Y1.2(#2) A_5_Y1.4(#4)
A_5_I2C_SCL: A_5_TB2.2 A_5_TB3.2 A_5_U1.B1(I2CSCL)
A_5_I2C_SDA: A_5_TB2.3 A_5_TB3.3 A_5_U1.C1(I2CSDA)
A_5_IRQ: A_5_TB2.4 A_5_TB3.4 A_5_U1.D1(IRQ)
A_5_N2189999: A_5_C15.2 A_5_C17.1 A_5_C50.1 A_5_C54.2 A_5_R53.2 A_5_R55.1
A_5_N2190055: A_5_C16.2 A_5_C18.2 A_5_C51.2 A_5_C55.2 A_5_R54.2 A_5_R56.1
A_5_N2190079: A_5_C13.1 A_5_C15.1 A_5_C54.1 A_5_L1.2 A_5_R1.1
A_5_N2190159: A_5_C12.2 A_5_C52.2 A_5_R56.2 A_5_R73.1 A_5_TB1.3
A_5_N2190199: A_5_C11.2 A_5_C53.2 A_5_R55.2 A_5_R75.1 A_5_TB1.1
A_5_N2190513: A_5_C14.2 A_5_C16.1 A_5_C55.1 A_5_L2.2 A_5_R2.2
A_5_N2190991: A_5_L104.1 A_5_L104.2 A_5_R73.2 A_5_R75.2
A_5_N2198580: A_5_R23.1 A_5_R24.2 A_5_U1.B2(I2CADR0)
A_5_N2222470: A_5_C20.2 A_5_R2.1 A_5_R54.1
A_5_N2227379: A_5_C19.2 A_5_R1.2 A_5_R53.1
A_5_N2256986: A_5_C57.1 A_5_U1.A3(XTAL1) A_5_Y1.3(#3)
A_5_N2256988: A_5_C56.1 A_5_U1.C3(XTAL2) A_5_Y1.1(#1)
A_5_N2257197: A_5_R32.2 A_5_U1.A1(TST1)
A_5_N2257995: A_5_C1.1 A_5_C22.1 A_5_U1.C6(VDD)
A_5_N2259746: A_5_C7.1 A_5_C10.1 A_5_U1.E7(TVDD)
A_5_N2259753: A_5_C8.1 A_5_U1.D7(VDHF)
A_5_N2259760: A_5_C6.1 A_5_U1.F7(VMID)
A_5_PVDD: A_5_C2.1 A_5_C3.1 A_5_C9.1 A_5_C21.1 A_5_R23.2 A_5_TB2.1 A_5_TB3.1 A_5_U1.C7(VBAT) A_5_U1.D3(PVDD) A_5_U1.G1(VBAT2) A_5_U1.G2(VUP)
A_5_RXN: A_5_C20.1 A_5_U1.F5(RXN)
A_5_RXP: A_5_C19.1 A_5_U1.F6(RXP)
A_5_TX1: A_5_L1.1 A_5_U1.G3(TX1)
A_5_TX2: A_5_L2.1 A_5_U1.G5(TX2)
A_5_VEN: A_5_TB2.5 A_5_TB3.5 A_5_U1.E1(VEN)
A_6_ANT1: A_6_C11.1 A_6_C53.1 A_6_U1.G7(ANT1)
A_6_ANT2: A_6_C12.1 A_6_C52.1 A_6_U1.G6(ANT2)
A_6_GND: A_6_C1.2 A_6_C2.2 A_6_C3.2 A_6_C6.2 A_6_C7.2 A_6_C8.2 A_6_C9.2 A_6_C10.2 A_6_C13.2 A_6_C14.1 A_6_C17.2 A_6_C18.1 A_6_C21.2 A_6_C22.2 A_6_C50.2 A_6_C51.1 A_6_C56.2 A_6_C57.2 A_6_R24.1 A_6_R32.1 A_6_SH1.1 A_6_SH1.2 A_6_SH1.3 A_6_SH1.4 A_6_SH1.5 A_6_SH1.6 A_6_SH1.7 A_6_SH1.8 A_6_TB1.2 A_6_TB2.6 A_6_TB3.6 A_6_U1.B5(TST2) A_6_U1.B6(VSS1) A_6_U1.C2(PVSS) A_6_U1.C4(VSS) A_6_U1.D4(VSS2) A_6_U1.D6(VSS3) A_6_U1.E2(DCDC_VSS) A_6_U1.F3(VSS4) A_6_U1.G4(TVSS) A_6_Y1.2(#2) A_6_Y1.4(#4)
A_6_I2C_SCL: A_6_TB2.2 A_6_TB3.2 A_6_U1.B1(I2CSCL)
A_6_I2C_SDA: A_6_TB2.3 A_6_TB3.3 A_6_U1.C1(I2CSDA)
A_6_IRQ: A_6_TB2.4 A_6_TB3.4 A_6_U1.D1(IRQ)
A_6_N2189999: A_6_C15.2 A_6_C17.1 A_6_C50.1 A_6_C54.2 A_6_R53.2 A_6_R55.1
A_6_N2190055: A_6_C16.2 A_6_C18.2 A_6_C51.2 A_6_C55.2 A_6_R54.2 A_6_R56.1
A_6_N2190079: A_6_C13.1 A_6_C15.1 A_6_C54.1 A_6_L1.2 A_6_R1.1
A_6_N2190159: A_6_C12.2 A_6_C52.2 A_6_R56.2 A_6_R73.1 A_6_TB1.3
A_6_N2190199: A_6_C11.2 A_6_C53.2 A_6_R55.2 A_6_R75.1 A_6_TB1.1
A_6_N2190513: A_6_C14.2 A_6_C16.1 A_6_C55.1 A_6_L2.2 A_6_R2.2
A_6_N2190991: A_6_L104.1 A_6_L104.2 A_6_R73.2 A_6_R75.2
A_6_N2198580: A_6_R23.1 A_6_R24.2 A_6_U1.B2(I2CADR0)
A_6_N2222470: A_6_C20.2 A_6_R2.1 A_6_R54.1
A_6_N2227379: A_6_C19.2 A_6_R1.2 A_6_R53.1
A_6_N2256986: A_6_C57.1 A_6_U1.A3(XTAL1) A_6_Y1.3(#3)
A_6_N2256988: A_6_C56.1 A_6_U1.C3(XTAL2) A_6_Y1.1(#1)
A_6_N2257197: A_6_R32.2 A_6_U1.A1(TST1)
A_6_N2257995: A_6_C1.1 A_6_C22.1 A_6_U1.C6(VDD)
A_6_N2259746: A_6_C7.1 A_6_C10.1 A_6_U1.E7(TVDD)
A_6_N2259753: A_6_C8.1 A_6_U1.D7(VDHF)
A_6_N2259760: A_6_C6.1 A_6_U1.F7(VMID)
A_6_PVDD: A_6_C2.1 A_6_C3.1 A_6_C9.1 A_6_C21.1 A_6_R23.2 A_6_TB2.1 A_6_TB3.1 A_6_U1.C7(VBAT) A_6_U1.D3(PVDD) A_6_U1.G1(VBAT2) A_6_U1.G2(VUP)
A_6_RXN: A_6_C20.1 A_6_U1.F5(RXN)
A_6_RXP: A_6_C19.1 A_6_U1.F6(RXP)
A_6_TX1: A_6_L1.1 A_6_U1.G3(TX1)
A_6_TX2: A_6_L2.1 A_6_U1.G5(TX2)
A_6_VEN: A_6_TB2.5 A_6_TB3.5 A_6_U1.E1(VEN)
B_1__SYS_5V: B_1_J9.C8(_SYS_5V)
B_1__VDD_5V: B_1_J9.C6(_VDD_5V)
B_1_GND_2272419: B_1_J8.C1(GND#C1) B_1_J8.C2(GND#C2) B_1_J9.C1(GND#C1) B_1_J9.C2(GND#C2) B_1_J9.C43(GND#C43) B_1_J9.C44(GND#C44) B_1_J9.C45(GND#C45) B_1_J9.C46(GND#C46) B_1_TB8.6 B_1_TB9.6
B_1_I2C_SCL_2272419: B_1_J9.C19(I2C2_SCL) B_1_TB9.2
B_1_I2C_SDA_2272319: B_1_J9.C20(I2C2_SDA) B_1_TB9.3
B_1_IRQ_2273337: B_1_J8.C26(GPIO1_29) B_1_TB8.4
B_1_SYS_5V: B_1_J9.C7(SYS_5V)
B_1_VBAT_PVDD: B_1_J9.C3(DC_3V3#C3) B_1_J9.C4(DC_3V3#C4) B_1_TB9.1
B_1_VDD_5V: B_1_J9.C5(VDD_5V)
B_1_VEN_2272419: B_1_J9.C11(UART4_RXD) B_1_TB9.5
B_2__SYS_5V: B_2_J9.C8(_SYS_5V)
B_2__VDD_5V: B_2_J9.C6(_VDD_5V)
B_2_GND_2272419: B_2_J8.C1(GND#C1) B_2_J8.C2(GND#C2) B_2_J9.C1(GND#C1) B_2_J9.C2(GND#C2) B_2_J9.C43(GND#C43) B_2_J9.C44(GND#C44) B_2_J9.C45(GND#C45) B_2_J9.C46(GND#C46) B_2_TB8.6 B_2_TB9.6
B_2_I2C_SCL_2272419: B_2_J9.C19(I2C2_SCL) B_2_TB9.2
B_2_I2C_SDA_2272319: B_2_J9.C20(I2C2_SDA) B_2_TB9.3
B_2_IRQ_2273337: B_2_J8.C26(GPIO1_29) B_2_TB8.4
B_2_SYS_5V: B_2_J9.C7(SYS_5V)
B_2_VBAT_PVDD: B_2_J9.C3(DC_3V3#C3) B_2_J9.C4(DC_3V3#C4) B_2_TB9.1
B_2_VDD_5V: B_2_J9.C5(VDD_5V)
B_2_VEN_2272419: B_2_J9.C11(UART4_RXD) B_2_TB9.5
B_3__SYS_5V: B_3_J9.C8(_SYS_5V)
B_3__VDD_5V: B_3_J9.C6(_VDD_5V)
B_3_GND_2272419: B_3_J8.C1(GND#C1) B_3_J8.C2(GND#C2) B_3_J9.C1(GND#C1) B_3_J9.C2(GND#C2) B_3_J9.C43(GND#C43) B_3_J9.C44(GND#C44) B_3_J9.C45(GND#C45) B_3_J9.C46(GND#C46) B_3_TB8.6 B_3_TB9.6
B_3_I2C_SCL_2272419: B_3_J9.C19(I2C2_SCL) B_3_TB9.2
B_3_I2C_SDA_2272319: B_3_J9.C20(I2C2_SDA) B_3_TB9.3
B_3_IRQ_2273337: B_3_J8.C26(GPIO1_29) B_3_TB8.4
B_3_SYS_5V: B_3_J9.C7(SYS_5V)
B_3_VBAT_PVDD: B_3_J9.C3(DC_3V3#C3) B_3_J9.C4(DC_3V3#C4) B_3_TB9.1
B_3_VDD_5V: B_3_J9.C5(VDD_5V)
B_3_VEN_2272419: B_3_J9.C11(UART4_RXD) B_3_TB9.5
B_4__SYS_5V: B_4_J9.C8(_SYS_5V)
B_4__VDD_5V: B_4_J9.C6(_VDD_5V)
B_4_GND_2272419: B_4_J8.C1(GND#C1) B_4_J8.C2(GND#C2) B_4_J9.C1(GND#C1) B_4_J9.C2(GND#C2) B_4_J9.C43(GND#C43) B_4_J9.C44(GND#C44) B_4_J9.C45(GND#C45) B_4_J9.C46(GND#C46) B_4_TB8.6 B_4_TB9.6
B_4_I2C_SCL_2272419: B_4_J9.C19(I2C2_SCL) B_4_TB9.2
B_4_I2C_SDA_2272319: B_4_J9.C20(I2C2_SDA) B_4_TB9.3
B_4_IRQ_2273337: B_4_J8.C26(GPIO1_29) B_4_TB8.4
B_4_SYS_5V: B_4_J9.C7(SYS_5V)
B_4_VBAT_PVDD: B_4_J9.C3(DC_3V3#C3) B_4_J9.C4(DC_3V3#C4) B_4_TB9.1
B_4_VDD_5V: B_4_J9.C5(VDD_5V)
B_4_VEN_2272419: B_4_J9.C11(UART4_RXD) B_4_TB9.5
B_5__SYS_5V: B_5_J9.C8(_SYS_5V)
B_5__VDD_5V: B_5_J9.C6(_VDD_5V)
B_5_GND_2272419: B_5_J8.C1(GND#C1) B_5_J8.C2(GND#C2) B_5_J9.C1(GND#C1) B_5_J9.C2(GND#C2) B_5_J9.C43(GND#C43) B_5_J9.C44(GND#C44) B_5_J9.C45(GND#C45) B_5_J9.C46(GND#C46) B_5_TB8.6 B_5_TB9.6
B_5_I2C_SCL_2272419: B_5_J9.C19(I2C2_SCL) B_5_TB9.2
B_5_I2C_SDA_2272319: B_5_J9.C20(I2C2_SDA) B_5_TB9.3
B_5_IRQ_2273337: B_5_J8.C26(GPIO1_29) B_5_TB8.4
B_5_SYS_5V: B_5_J9.C7(SYS_5V)
B_5_VBAT_PVDD: B_5_J9.C3(DC_3V3#C3) B_5_J9.C4(DC_3V3#C4) B_5_TB9.1
B_5_VDD_5V: B_5_J9.C5(VDD_5V)
B_5_VEN_2272419: B_5_J9.C11(UART4_RXD) B_5_TB9.5
C_1_5V: C_1_J1.2(5V)
C_1__5V: C_1_J1.4(_5V)
C_1_GND_2270869: C_1_J1.6(GND#6) C_1_J1.9(GND#9) C_1_J1.14(GND#14) C_1_J1.20(GND#20) C_1_J1.25(GND#25) C_1_TB4.6 C_1_TB5.6
C_1_I2C_SCL_2270949: C_1_J1.5(SCL) C_1_TB5.2
C_1_I2C_SDA_2270933: C_1_J1.3(SDA) C_1_TB5.3
C_1_IRQ_2270913: C_1_J1.16(GPIO23) C_1_TB5.4
C_1_VBAT_PVDD_2271009: C_1_J1.1(3V3#1) C_1_J1.17(3V3#17) C_1_TB5.1
C_1_VEN_2270923: C_1_J1.18(GPIO24) C_1_TB5.5
C_2_5V: C_2_J1.2(5V)
C_2__5V: C_2_J1.4(_5V)
C_2_GND_2270869: C_2_J1.6(GND#6) C_2_J1.9(GND#9) C_2_J1.14(GND#14) C_2_J1.20(GND#20) C_2_J1.25(GND#25) C_2_TB4.6 C_2_TB5.6
C_2_I2C_SCL_2270949: C_2_J1.5(SCL) C_2_TB5.2
C_2_I2C_SDA_2270933: C_2_J1.3(SDA) C_2_TB5.3
C_2_IRQ_2270913: C_2_J1.16(GPIO23) C_2_TB5.4
C_2_VBAT_PVDD_2271009: C_2_J1.1(3V3#1) C_2_J1.17(3V3#17) C_2_TB5.1
C_2_VEN_2270923: C_2_J1.18(GPIO24) C_2_TB5.5
C_3_5V: C_3_J1.2(5V)
C_3__5V: C_3_J1.4(_5V)
C_3_GND_2270869: C_3_J1.6(GND#6) C_3_J1.9(GND#9) C_3_J1.14(GND#14) C_3_J1.20(GND#20) C_3_J1.25(GND#25) C_3_TB4.6 C_3_TB5.6
C_3_I2C_SCL_2270949: C_3_J1.5(SCL) C_3_TB5.2
C_3_I2C_SDA_2270933: C_3_J1.3(SDA) C_3_TB5.3
C_3_IRQ_2270913: C_3_J1.16(GPIO23) C_3_TB5.4
C_3_VBAT_PVDD_2271009: C_3_J1.1(3V3#1) C_3_J1.17(3V3#17) C_3_TB5.1
C_3_VEN_2270923: C_3_J1.18(GPIO24) C_3_TB5.5
C_4_5V: C_4_J1.2(5V)
C_4__5V: C_4_J1.4(_5V)
C_4_GND_2270869: C_4_J1.6(GND#6) C_4_J1.9(GND#9) C_4_J1.14(GND#14) C_4_J1.20(GND#20) C_4_J1.25(GND#25) C_4_TB4.6 C_4_TB5.6
C_4_I2C_SCL_2270949: C_4_J1.5(SCL) C_4_TB5.2
C_4_I2C_SDA_2270933: C_4_J1.3(SDA) C_4_TB5.3
C_4_IRQ_2270913: C_4_J1.16(GPIO23) C_4_TB5.4
C_4_VBAT_PVDD_2271009: C_4_J1.1(3V3#1) C_4_J1.17(3V3#17) C_4_TB5.1
C_4_VEN_2270923: C_4_J1.18(GPIO24) C_4_TB5.5
C_5_5V: C_5_J1.2(5V)
C_5__5V: C_5_J1.4(_5V)
C_5_GND_2270869: C_5_J1.6(GND#6) C_5_J1.9(GND#9) C_5_J1.14(GND#14) C_5_J1.20(GND#20) C_5_J1.25(GND#25) C_5_TB4.6 C_5_TB5.6
C_5_I2C_SCL_2270949: C_5_J1.5(SCL) C_5_TB5.2
C_5_I2C_SDA_2270933: C_5_J1.3(SDA) C_5_TB5.3
C_5_IRQ_2270913: C_5_J1.16(GPIO23) C_5_TB5.4
C_5_VBAT_PVDD_2271009: C_5_J1.1(3V3#1) C_5_J1.17(3V3#17) C_5_TB5.1
C_5_VEN_2270923: C_5_J1.18(GPIO24) C_5_TB5.5

Pads without a net: A_1_1 1; A_1_TB2 7 8; A_1_TB10 1 2 3; A_1_U1 A2 A4 A5 A6 A7 B3 B4 B7 C5 D2 D5 E3 E4 E5 E6 F1 F2 F4; A_2_1 1; A_2_TB2 7 8; A_2_TB10 1 2 3; A_2_U1 A2 A4 A5 A6 A7 B3 B4 B7 C5 D2 D5 E3 E4 E5 E6 F1 F2 F4; A_3_1 1; A_3_TB2 7 8; A_3_TB10 1 2 3; A_3_U1 A2 A4 A5 A6 A7 B3 B4 B7 C5 D2 D5 E3 E4 E5 E6 F1 F2 F4; A_4_1 1; A_4_TB2 7 8; A_4_TB10 1 2 3; A_4_U1 A2 A4 A5 A6 A7 B3 B4 B7 C5 D2 D5 E3 E4 E5 E6 F1 F2 F4; A_5_1 1; A_5_TB2 7 8; A_5_TB10 1 2 3; A_5_U1 A2 A4 A5 A6 A7 B3 B4 B7 C5 D2 D5 E3 E4 E5 E6 F1 F2 F4; A_6_1 1; A_6_TB2 7 8; A_6_TB10 1 2 3; A_6_U1 A2 A4 A5 A6 A7 B3 B4 B7 C5 D2 D5 E3 E4 E5 E6 F1 F2 F4; B_1_2 1; B_1_J8 C3 C4 C5 C6 C7 C8 C9 C10 C11 C12 C13 C14 C15 C16 C17 C18 C19 C20 C21 C22 C23 C24 C25 C27 C28 C29 C30 C31 C32 C33 C34 C35 C36 C37 C38 C39 C40 C41 C42 C43 C44 C45 C46; B_1_J9 C9 C10 C12 C13 C14 C15 C16 C17 C18 C21 C22 C23 C24 C25 C26 C27 C28 C29 C30 C31 C32 C33 C34 C35 C36 C37 C38 C39 C40 C41 C42; B_1_TB8 1 2 3 5; B_1_TB9 4 7 8; B_1_TB11 1 2 3; B_2_2 1; B_2_J8 C3 C4 C5 C6 C7 C8 C9 C10 C11 C12 C13 C14 C15 C16 C17 C18 C19 C20 C21 C22 C23 C24 C25 C27 C28 C29 C30 C31 C32 C33 C34 C35 C36 C37 C38 C39 C40 C41 C42 C43 C44 C45 C46; B_2_J9 C9 C10 C12 C13 C14 C15 C16 C17 C18 C21 C22 C23 C24 C25 C26 C27 C28 C29 C30 C31 C32 C33 C34 C35 C36 C37 C38 C39 C40 C41 C42; B_2_TB8 1 2 3 5; B_2_TB9 4 7 8; B_2_TB11 1 2 3; B_3_2 1; B_3_J8 C3 C4 C5 C6 C7 C8 C9 C10 C11 C12 C13 C14 C15 C16 C17 C18 C19 C20 C21 C22 C23 C24 C25 C27 C28 C29 C30 C31 C32 C33 C34 C35 C36 C37 C38 C39 C40 C41 C42 C43 C44 C45 C46; B_3_J9 C9 C10 C12 C13 C14 C15 C16 C17 C18 C21 C22 C23 C24 C25 C26 C27 C28 C29 C30 C31 C32 C33 C34 C35 C36 C37 C38 C39 C40 C41 C42; B_3_TB8 1 2 3 5; B_3_TB9 4 7 8; B_3_TB11 1 2 3; B_4_2 1; B_4_J8 C3 C4 C5 C6 C7 C8 C9 C10 C11 C12 C13 C14 C15 C16 C17 C18 C19 C20 C21 C22 C23 C24 C25 C27 C28 C29 C30 C31 C32 C33 C34 C35 C36 C37 C38 C39 C40 C41 C42 C43 C44 C45 C46; B_4_J9 C9 C10 C12 C13 C14 C15 C16 C17 C18 C21 C22 C23 C24 C25 C26 C27 C28 C29 C30 C31 C32 C33 C34 C35 C36 C37 C38 C39 C40 C41 C42; B_4_TB8 1 2 3 5; B_4_TB9 4 7 8; B_4_TB11 1 2 3; B_5_2 1; B_5_J8 C3 C4 C5 C6 C7 C8 C9 C10 C11 C12 C13 C14 C15 C16 C17 C18 C19 C20 C21 C22 C23 C24 C25 C27 C28 C29 C30 C31 C32 C33 C34 C35 C36 C37 C38 C39 C40 C41 C42 C43 C44 C45 C46; B_5_J9 C9 C10 C12 C13 C14 C15 C16 C17 C18 C21 C22 C23 C24 C25 C26 C27 C28 C29 C30 C31 C32 C33 C34 C35 C36 C37 C38 C39 C40 C41 C42; B_5_TB8 1 2 3 5; B_5_TB9 4 7 8; B_5_TB11 1 2 3; C_1_3 1; C_1_4 1; C_1_5 1; C_1_6 1; C_1_J1 7 8 10 11 12 13 15 19 21 22 23 24 26; C_1_TB4 1 2 3 4 5 7 8; C_1_TB12 1 2 3; C_2_3 1; C_2_4 1; C_2_5 1; C_2_6 1; C_2_J1 7 8 10 11 12 13 15 19 21 22 23 24 26; C_2_TB4 1 2 3 4 5 7 8; C_2_TB12 1 2 3; C_3_3 1; C_3_4 1; C_3_5 1; C_3_6 1; C_3_J1 7 8 10 11 12 13 15 19 21 22 23 24 26; C_3_TB4 1 2 3 4 5 7 8; C_3_TB12 1 2 3; C_4_3 1; C_4_4 1; C_4_5 1; C_4_6 1; C_4_J1 7 8 10 11 12 13 15 19 21 22 23 24 26; C_4_TB4 1 2 3 4 5 7 8; C_4_TB12 1 2 3; C_5_3 1; C_5_4 1; C_5_5 1; C_5_6 1; C_5_J1 7 8 10 11 12 13 15 19 21 22 23 24 26; C_5_TB4 1 2 3 4 5 7 8; C_5_TB12 1 2 3

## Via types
v1: diameter 4.445, hole 3.2, TOP to BOTTOM, 20 vias
v2: diameter 0.62, hole 0.31, TOP to BOTTOM, 1264 vias
v3: diameter 0.28, hole 0.1, TOP to IS1, 198 vias

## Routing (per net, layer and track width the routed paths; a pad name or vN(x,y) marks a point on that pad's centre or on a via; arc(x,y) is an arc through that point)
A_1_ANT1: length 13.9
  TOP w0.2: A_1_U1.G7 24.18,178.3 v3(24.18,178.32)
  TOP w0.5: A_1_C11.1 A_1_C53.1 32.95,183.3 v2(32.7,183.05)
  IS1 w0.15: v3(24.18,178.32) 24.36,178.5 26.6,178.5 27.15,179.05 29,179.05 32.7,182.75 v2(32.7,183.05)
A_1_ANT2: length 11.5
  TOP w0.2: A_1_U1.G6 24.65,178.35 24.65,178.5 24.15,179 v3(23.95,179)
  TOP w0.5: v2(18.7,183.05) 18.45,183.3 A_1_C52.1 A_1_C12.1
  IS1 w0.15: v3(23.95,179) 22.5,179 18.7,182.8 v2(18.7,183.05)
A_1_GND: length 200.9
  TOP w0.2: v3(26.9,174.85) v3(27.85,173.9) 28.26,173.49 A_1_R32.1 ; v2(25.7,179.05) 25.7,181.6
  TOP w0.3: 21.21,173.3 A_1_C1.2 21.89,172.57 ; A_1_C13.2 26.43,182.49 ; 11.1,175.17 A_1_SH1.1 ; A_1_SH1.1 11.1,178.43 ; A_1_SH1.1 12.23,176.8 ; A_1_SH1.1 9.97,176.8 ; 28.55,172.81 A_1_R32.1 29.28,173.49 ; 9.97,189.5 A_1_SH1.8 ; A_1_SH1.8 11.1,191.13 ; A_1_SH1.8 12.23,189.5 ; A_1_SH1.8 11.1,187.87 ; 21.21,178.7 A_1_C6.2 ; A_1_SH1.5 38.83,188.6 ; A_1_SH1.5 37.7,190.23 ; A_1_SH1.5 37.7,186.97 ; A_1_SH1.5 36.57,188.6 ; A_1_C10.2 20.68,176.79 ; A_1_C10.2 19.22,176.79 ; A_1_C10.2 19.95,176.11 ; 28,190.77 A_1_SH1.6 ; A_1_SH1.6 26.37,191.9 ; A_1_SH1.6 29.63,191.9 ; 28.67,170.3 A_1_SH1.3 ; A_1_SH1.3 31.93,170.3 ; A_1_SH1.3 30.3,171.43 ; A_1_SH1.4 38.83,175.9 ; A_1_SH1.4 36.57,175.9 ; A_1_SH1.4 37.7,174.27 ; A_1_SH1.4 37.7,177.53 ; 21.21,175.3 A_1_C2.2 ; A_1_TB3.6 9.18,188.4 ; A_1_TB3.6 6.42,188.4 ; A_1_TB3.6 7.8,189.78 ; 30.21,177.43 A_1_C3.2 30.89,176.7 ; A_1_SH1.2 19.23,170.3 ; A_1_SH1.2 17.6,171.43 ; A_1_SH1.2 15.97,170.3 ; 13.67,191.9 A_1_SH1.7 ; A_1_SH1.7 16.93,191.9 ; A_1_SH1.7 15.3,190.77 ; 42.31,186.37 A_1_TB2.6 39.55,186.37 ; 29.47,173.64 A_1_R24.1 30.2,172.96 ; A_1_C9.2 30.19,177.7 ; 23.27,172.49 A_1_C56.2 24,171.81 ; 21.21,176.3 A_1_C8.2 ; 28.18,171.99 A_1_C57.2 27.45,171.31 ; 21.21,174.3 A_1_C22.2 ; A_1_U1.G4 v2(25.7,179.05) ; 21.21,177.3 A_1_C7.2 ; A_1_C21.2 30.19,178.7 ; A_1_C14.1 25,182.49 ; v3(25.7,176.3) A_1_U1.D4 ; 25.18,171.42 A_1_Y1.2
  TOP w0.4: 25.7,187.8 25.7,186.7
  TOP w0.5: A_1_C18.1 A_1_C51.1 A_1_C50.2 A_1_C17.2 ; A_1_C18.1 A_1_C17.2 ; A_1_C18.1 25,190.6 ; A_1_C17.2 26.43,190.6 ; A_1_C14.1 A_1_C13.2
  IS1 w0.3: A_1_SH1.8 12.23,189.5 ; A_1_SH1.8 11.1,190.63 ; A_1_SH1.8 9.97,189.5 ; A_1_SH1.8 11.1,188.37 ; 37.7,174.77 A_1_SH1.4 ; A_1_SH1.4 36.57,175.9 ; A_1_SH1.4 38.83,175.9 ; A_1_SH1.4 37.7,177.03 ; 39.6,186.37 A_1_TB2.6 42.26,186.37 ; A_1_SH1.5 38.83,188.6 ; A_1_SH1.5 37.7,189.73 ; A_1_SH1.5 37.7,187.47 ; A_1_SH1.5 36.57,188.6 ; A_1_SH1.6 29.13,191.9 ; A_1_SH1.6 28,190.77 ; A_1_SH1.6 26.87,191.9 ; A_1_TB3.6 9.13,188.4 ; A_1_TB3.6 7.8,189.73 ; A_1_TB3.6 6.47,188.4 ; A_1_SH1.1 12.23,176.8 ; A_1_SH1.1 11.1,177.93 ; A_1_SH1.1 11.1,175.67 ; A_1_SH1.1 9.97,176.8 ; 16.47,170.3 A_1_SH1.2 ; A_1_SH1.2 18.73,170.3 ; A_1_SH1.2 17.6,171.43 ; 15.3,190.77 A_1_SH1.7 ; A_1_SH1.7 14.17,191.9 ; A_1_SH1.7 16.43,191.9 ; A_1_SH1.3 30.3,171.43 ; A_1_SH1.3 29.17,170.3 ; A_1_SH1.3 31.43,170.3
  IS2 w0.3: 28,190.77 A_1_SH1.6 ; A_1_SH1.6 26.87,191.9 ; A_1_SH1.6 29.13,191.9 ; 39.6,186.37 A_1_TB2.6 42.26,186.37 ; 6.47,188.4 A_1_TB3.6 ; A_1_TB3.6 7.8,189.73 ; A_1_TB3.6 9.13,188.4 ; A_1_SH1.1 12.23,176.8 ; A_1_SH1.1 11.1,175.67 ; A_1_SH1.1 11.1,177.93 ; A_1_SH1.8 12.23,189.5 ; A_1_SH1.8 9.97,189.5 ; A_1_SH1.8 11.1,188.37 ; A_1_SH1.8 11.1,190.63 ; A_1_SH1.4 38.83,175.9 ; A_1_SH1.4 37.7,174.77 ; A_1_SH1.4 36.57,175.9 ; A_1_SH1.4 37.7,177.03 ; A_1_SH1.5 38.83,188.6 ; A_1_SH1.5 37.7,187.47 ; A_1_SH1.5 37.7,189.73 ; A_1_SH1.5 36.57,188.6 ; 15.3,190.77 A_1_SH1.7 ; A_1_SH1.7 14.17,191.9 ; A_1_SH1.7 16.43,191.9 ; 29.17,170.3 A_1_SH1.3 31.43,170.3 ; 16.47,170.3 A_1_SH1.2 18.73,170.3
  BOTTOM w0.3: 11.1,175.17 A_1_SH1.1 ; A_1_SH1.1 9.97,176.8 ; A_1_SH1.1 11.1,178.43 ; A_1_SH1.1 12.23,176.8 ; 37.7,186.97 A_1_SH1.5 ; A_1_SH1.5 37.7,190.23 ; A_1_SH1.5 36.57,188.6 ; A_1_SH1.5 38.83,188.6 ; A_1_SH1.3 31.93,170.3 ; A_1_SH1.3 30.3,171.43 ; A_1_SH1.3 28.67,170.3 ; 9.97,189.5 A_1_SH1.8 ; A_1_SH1.8 12.23,189.5 ; A_1_SH1.8 11.1,191.13 ; A_1_SH1.8 11.1,187.87 ; 26.37,191.9 A_1_SH1.6 ; A_1_SH1.6 29.63,191.9 ; A_1_SH1.6 28,190.77 ; A_1_SH1.7 16.93,191.9 ; A_1_SH1.7 15.3,190.77 ; A_1_SH1.7 13.67,191.9 ; 39.55,186.37 A_1_TB2.6 42.31,186.37 ; A_1_SH1.4 38.83,175.9 ; A_1_SH1.4 37.7,177.53 ; A_1_SH1.4 37.7,174.27 ; A_1_SH1.4 36.57,175.9 ; A_1_SH1.2 19.23,170.3 ; A_1_SH1.2 17.6,171.43 ; A_1_SH1.2 15.97,170.3 ; A_1_TB3.6 7.8,189.78 ; A_1_TB3.6 6.42,188.4 ; A_1_TB3.6 9.18,188.4
  vias: v2(6.1,189.85) v2(6.1,187.35) v2(6.1,184.85) v2(6.1,182.35) v2(6.1,179.85) v2(6.1,177.35) v2(6.1,174.85) v2(6.1,172.35) v2(6.1,169.85) v2(7.5,173.5) v2(7.5,171) v2(8.65,172.25) v2(8.6,169.85) v2(9.4,190.35) v2(9.6,186.75) v2(9.6,184.4) v2(9.6,182) v2(9.6,179.05) v2(9.6,175) v2(9.8,170.9) v2(9.95,192.55) v2(11.1,191.85) v2(11.1,187.3) v2(11.1,185.5) v2(11.1,183) v2(11.1,180.55) v2(11.1,173.5) v2(11.1,170.35) v2(11.95,192.6) v2(12.45,174.65) v2(12.65,190.5) v2(12.65,188) v2(12.65,185.5) v2(12.65,183.6) v2(13.25,178.5) v2(13.15,172.55) v2(13.45,175.8) v2(13.4,170.3) v2(13.6,192.6) v2(13.6,180.5) v2(14.05,189.3) v2(14.05,186.8) v2(14.05,184.3) v2(14.4,174.3) v2(15.15,190.5) v2(15.15,188) v2(15.15,185.5) v2(15.15,183) v2(15.15,181.1) v2(15.15,170.3) v2(15.5,176.15) v2(15.55,172.5) v2(15.9,178.15) v2(16.4,189.25) v2(16.4,186.75) v2(16.4,184.25) v2(16.4,181.75) v2(16.6,179.7) v2(16.75,174.3) v2(17,192.65) v2(17.25,187.55) v2(17.25,185.45) v2(17.45,189.3) v2(17.65,183) v2(17.65,180.5) v2(18.2,176) v2(18.2,174.3) v2(18.3,192.6) v2(18.3,172.5) v2(18.45,177.7) v2(18.95,189.05) v2(18.95,181.6) v2(19,187.45) v2(19,179.55) v2(19.4,190.7) v2(19.55,170.3) v2(19.65,183.5) v2(19.8,192.65) v2(20.15,180.5) v2(20.6,181.75) v2(20.65,183.5) v2(20.85,174.3) v2(20.8,172.5) v2(20.9,187.8) v2(20.95,176.2) v2(21.4,190.6) v2(21.9,192.55) v2(21.9,172.4) v2(22.15,170.25) v2(22.25,187.8) v2(23.2,191.9) v2(23.7,190.55) v2(24.25,192.6) v2(24.55,170.3) v2(25,183.55) v2(25,182.7) v2(25.6,191.9) v2(25.75,190.45) v2(26.3,192.65) v2(26.4,183.55) v2(26.4,182.7) v2(27.1,170.3) v2(28.15,190.5) v2(28.55,172.55) v2(29.2,187.75) v2(29.55,192.65) v2(30.05,190.5) v2(30.45,177.7) v2(30.5,187.75) v2(30.75,183.5) v2(30.8,181.7) v2(30.8,172.6) v2(31.6,192.6) v2(31.65,180.5) v2(31.65,176.7) v2(31.75,183.5) v2(32,190.5) v2(32.25,173) v2(32.4,189.15) v2(32.4,187.5) v2(32.5,191.9) v2(32.65,181.45) v2(33.45,171.4) v2(33.6,192.6) v2(33.7,177.85) v2(33.75,183) v2(33.75,180.5) v2(33.95,189.7) v2(34.05,186.7) v2(34.05,184.6) v2(34.4,170.3) v2(34.5,175.9) v2(35.05,191.9) v2(35.2,190.65) v2(35.2,188.7) v2(35.2,186.2) v2(35.2,183.7) v2(35.2,181.2) v2(35.65,174.85) v2(35.95,171.4) v2(36,179.55) v2(36.45,189.95) v2(36.45,187.45) v2(36.45,184.95) v2(36.45,182.45) v2(36.55,192.65) v2(37.65,191.85) v2(37.7,186.3) v2(37.7,183.7) v2(37.7,181.2) v2(37.7,179.1) v2(37.7,172.1) v2(37.7,170.3) v2(39.15,192.65) v2(39.15,190.15) v2(39.15,187.65) v2(39.15,185.15) v2(39.15,182.4) v2(39.15,180) v2(39.2,177.2) v2(39.2,173.8) v2(39.85,171.9) v2(39.85,169.85) v2(42.35,169.85) v2(42.8,177.65) v2(42.8,175.15) v2(42.9,192.65) v2(42.9,190.15) v2(42.9,187.65) v2(42.9,185.15) v2(42.9,182.65) v2(42.9,180.15) v2(42.9,172.95) v2(44.15,191.4) v2(44.15,188.9) v2(44.15,186.4) v2(44.15,183.9) v2(44.15,181.4) v2(44.15,178.9) v2(45.4,192.65) v2(45.4,190.15) v2(45.4,187.65) v2(45.4,185.15) v2(45.4,182.65) v2(45.4,180.15) v2(45.4,177.65) v2(45.4,175.15) v2(45.4,172.65) v3(24.7,176.8) v3(24.7,175.8) v3(24.95,172.4) v3(24.95,171.95) v3(25.2,175.8) v3(25.4,172.4) v3(25.4,171.95) v3(26,173.85) v3(26,173.3) v3(26.2,177.8) v3(26.45,173.85) v3(26.45,173.3) v3(26.7,177.3) v3(26.7,176.3)
